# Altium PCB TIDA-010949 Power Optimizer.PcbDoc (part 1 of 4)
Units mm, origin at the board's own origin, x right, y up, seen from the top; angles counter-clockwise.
Board outline 129.4 x 84 mm, 4 copper layers (Power1, Ground1, Ground2, Power2), stack 1.926 mm thick; 265 components, 128 nets, 802 pads, 1069 vias.
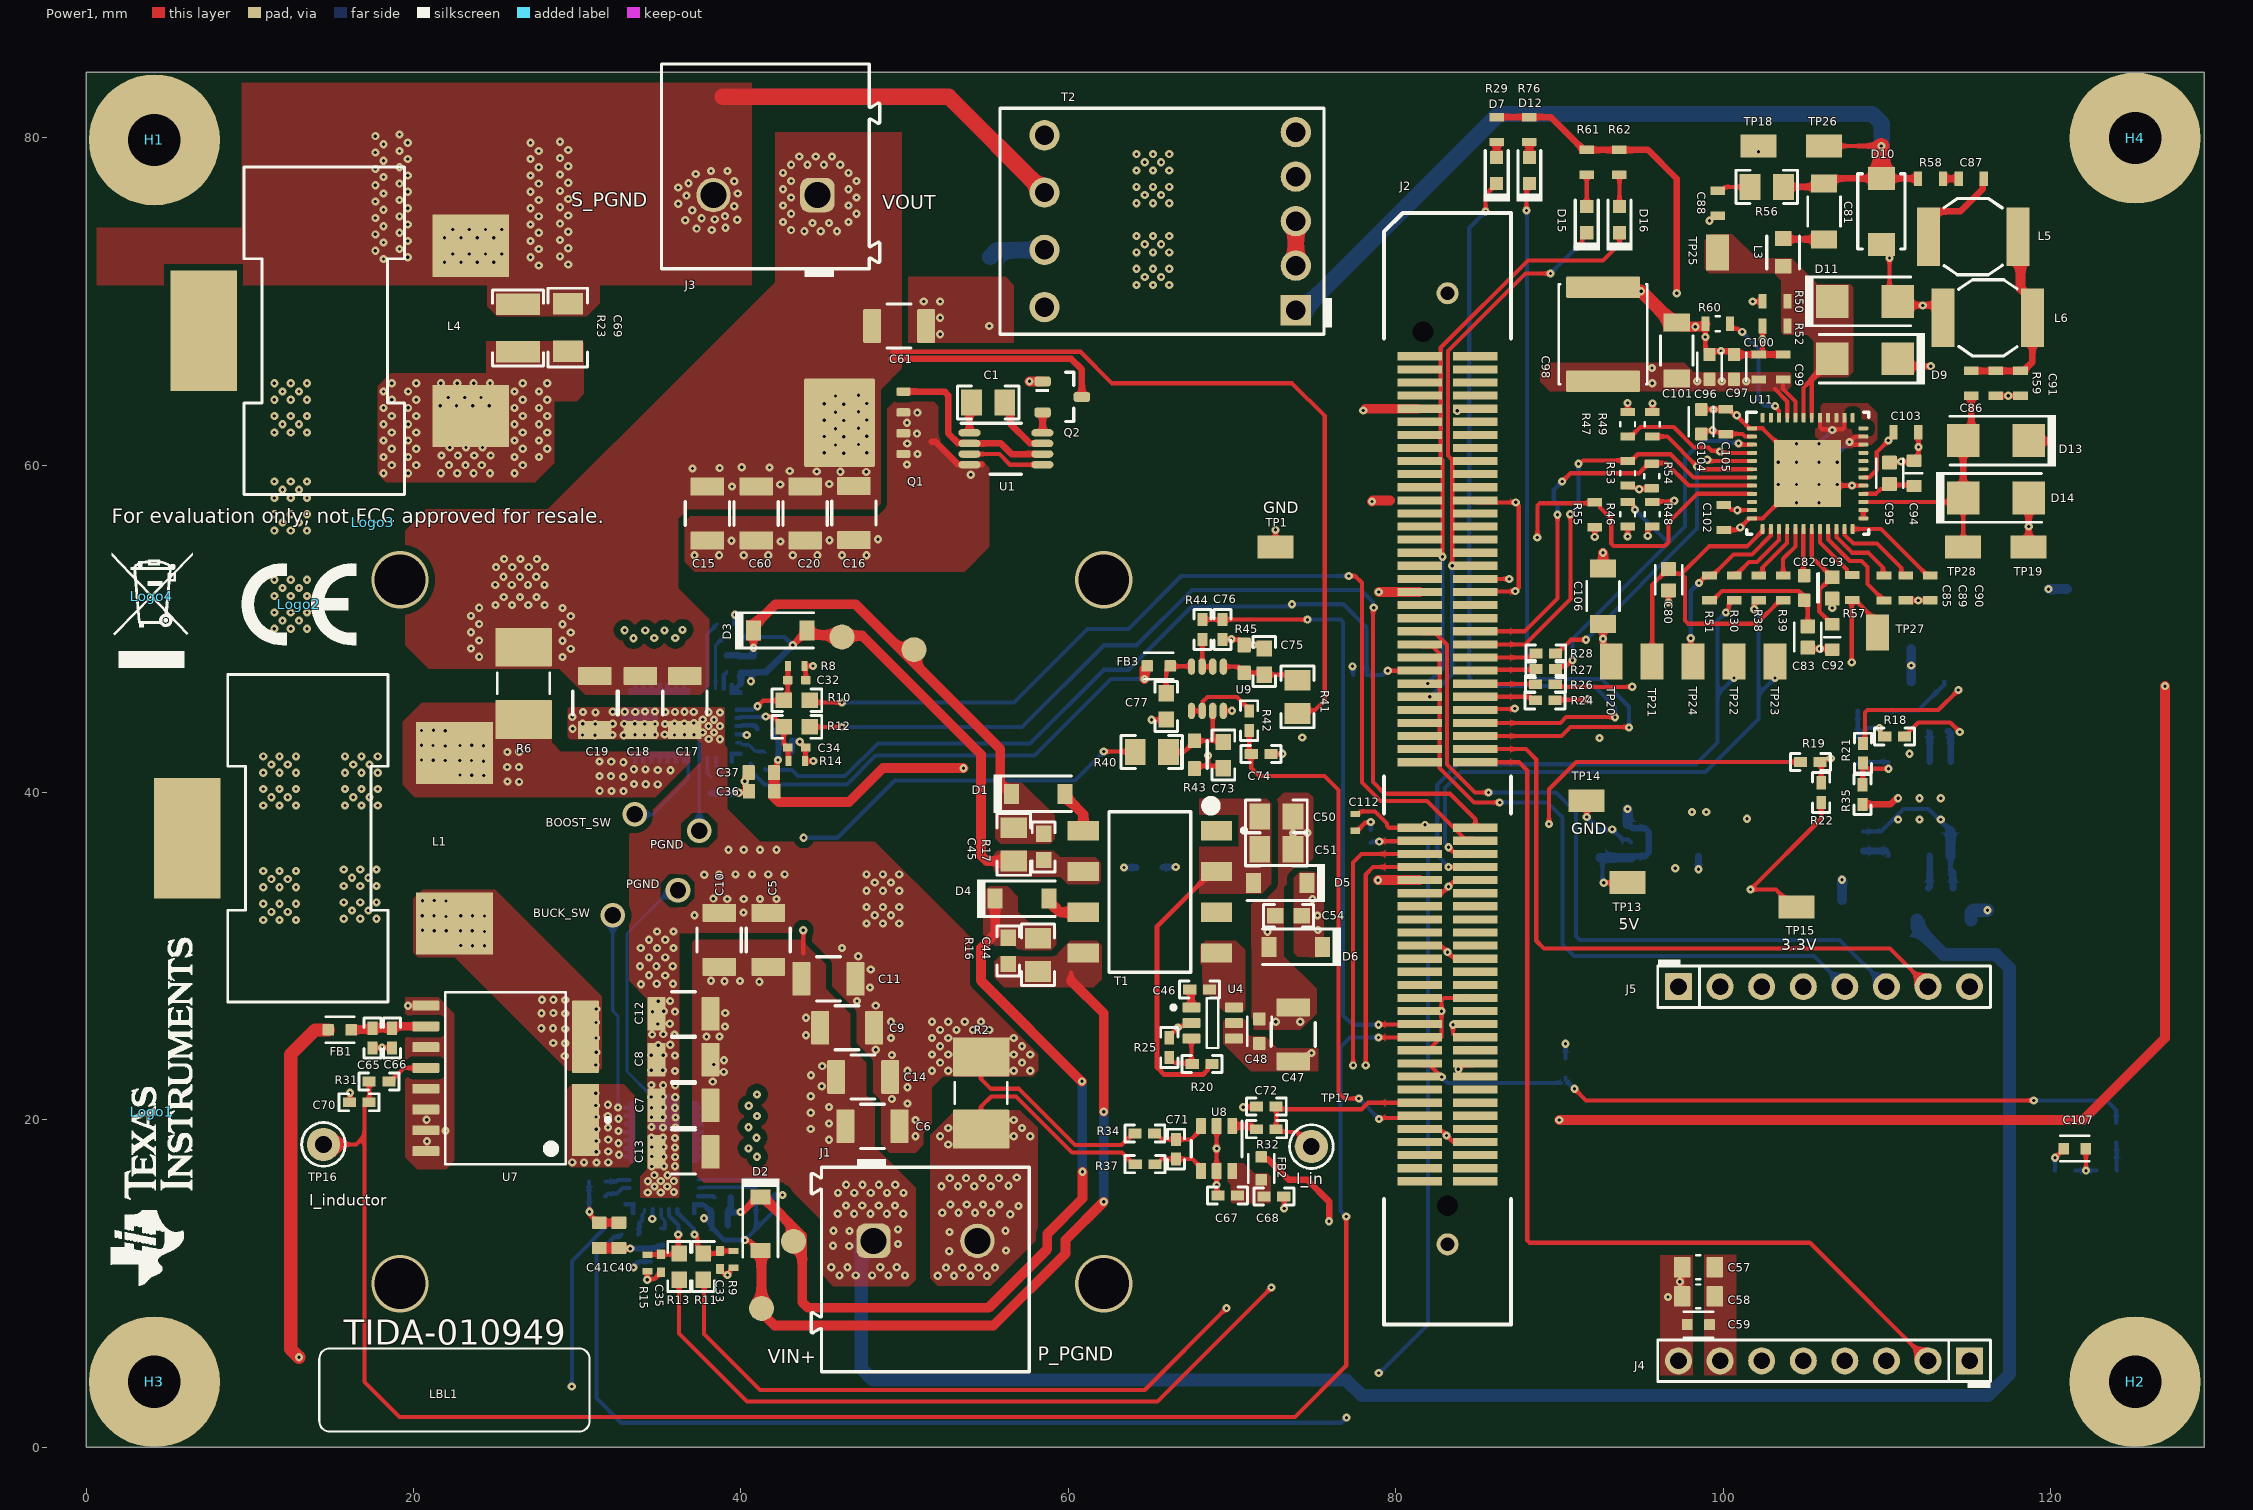
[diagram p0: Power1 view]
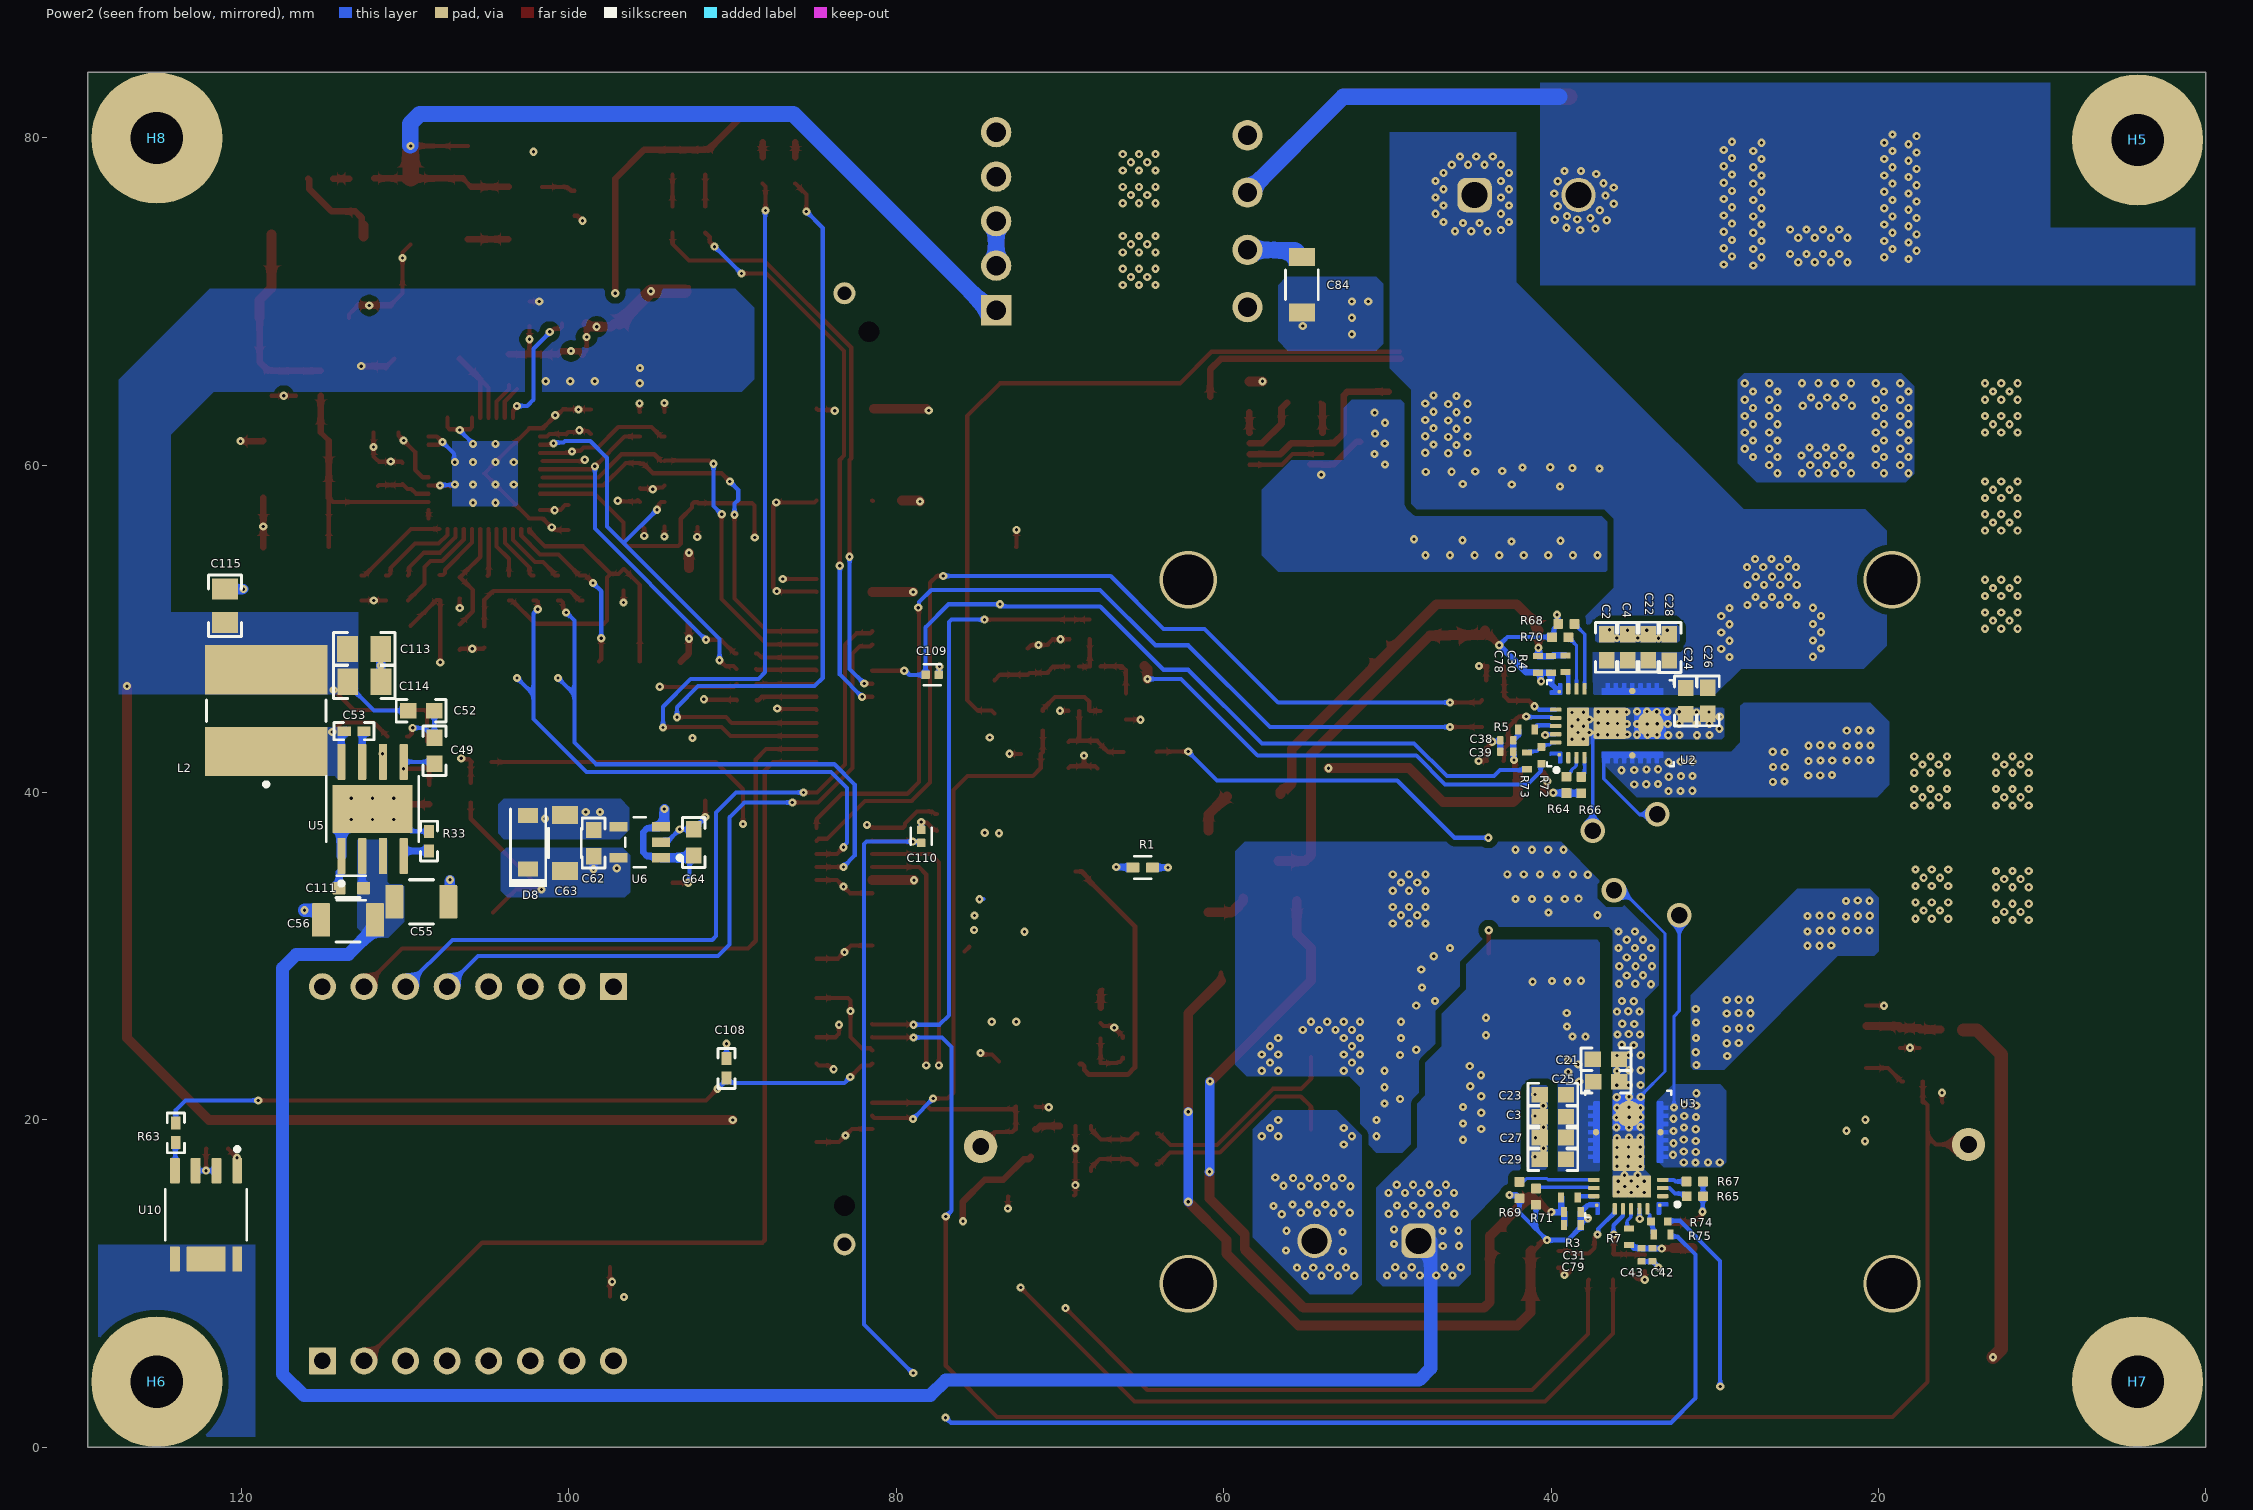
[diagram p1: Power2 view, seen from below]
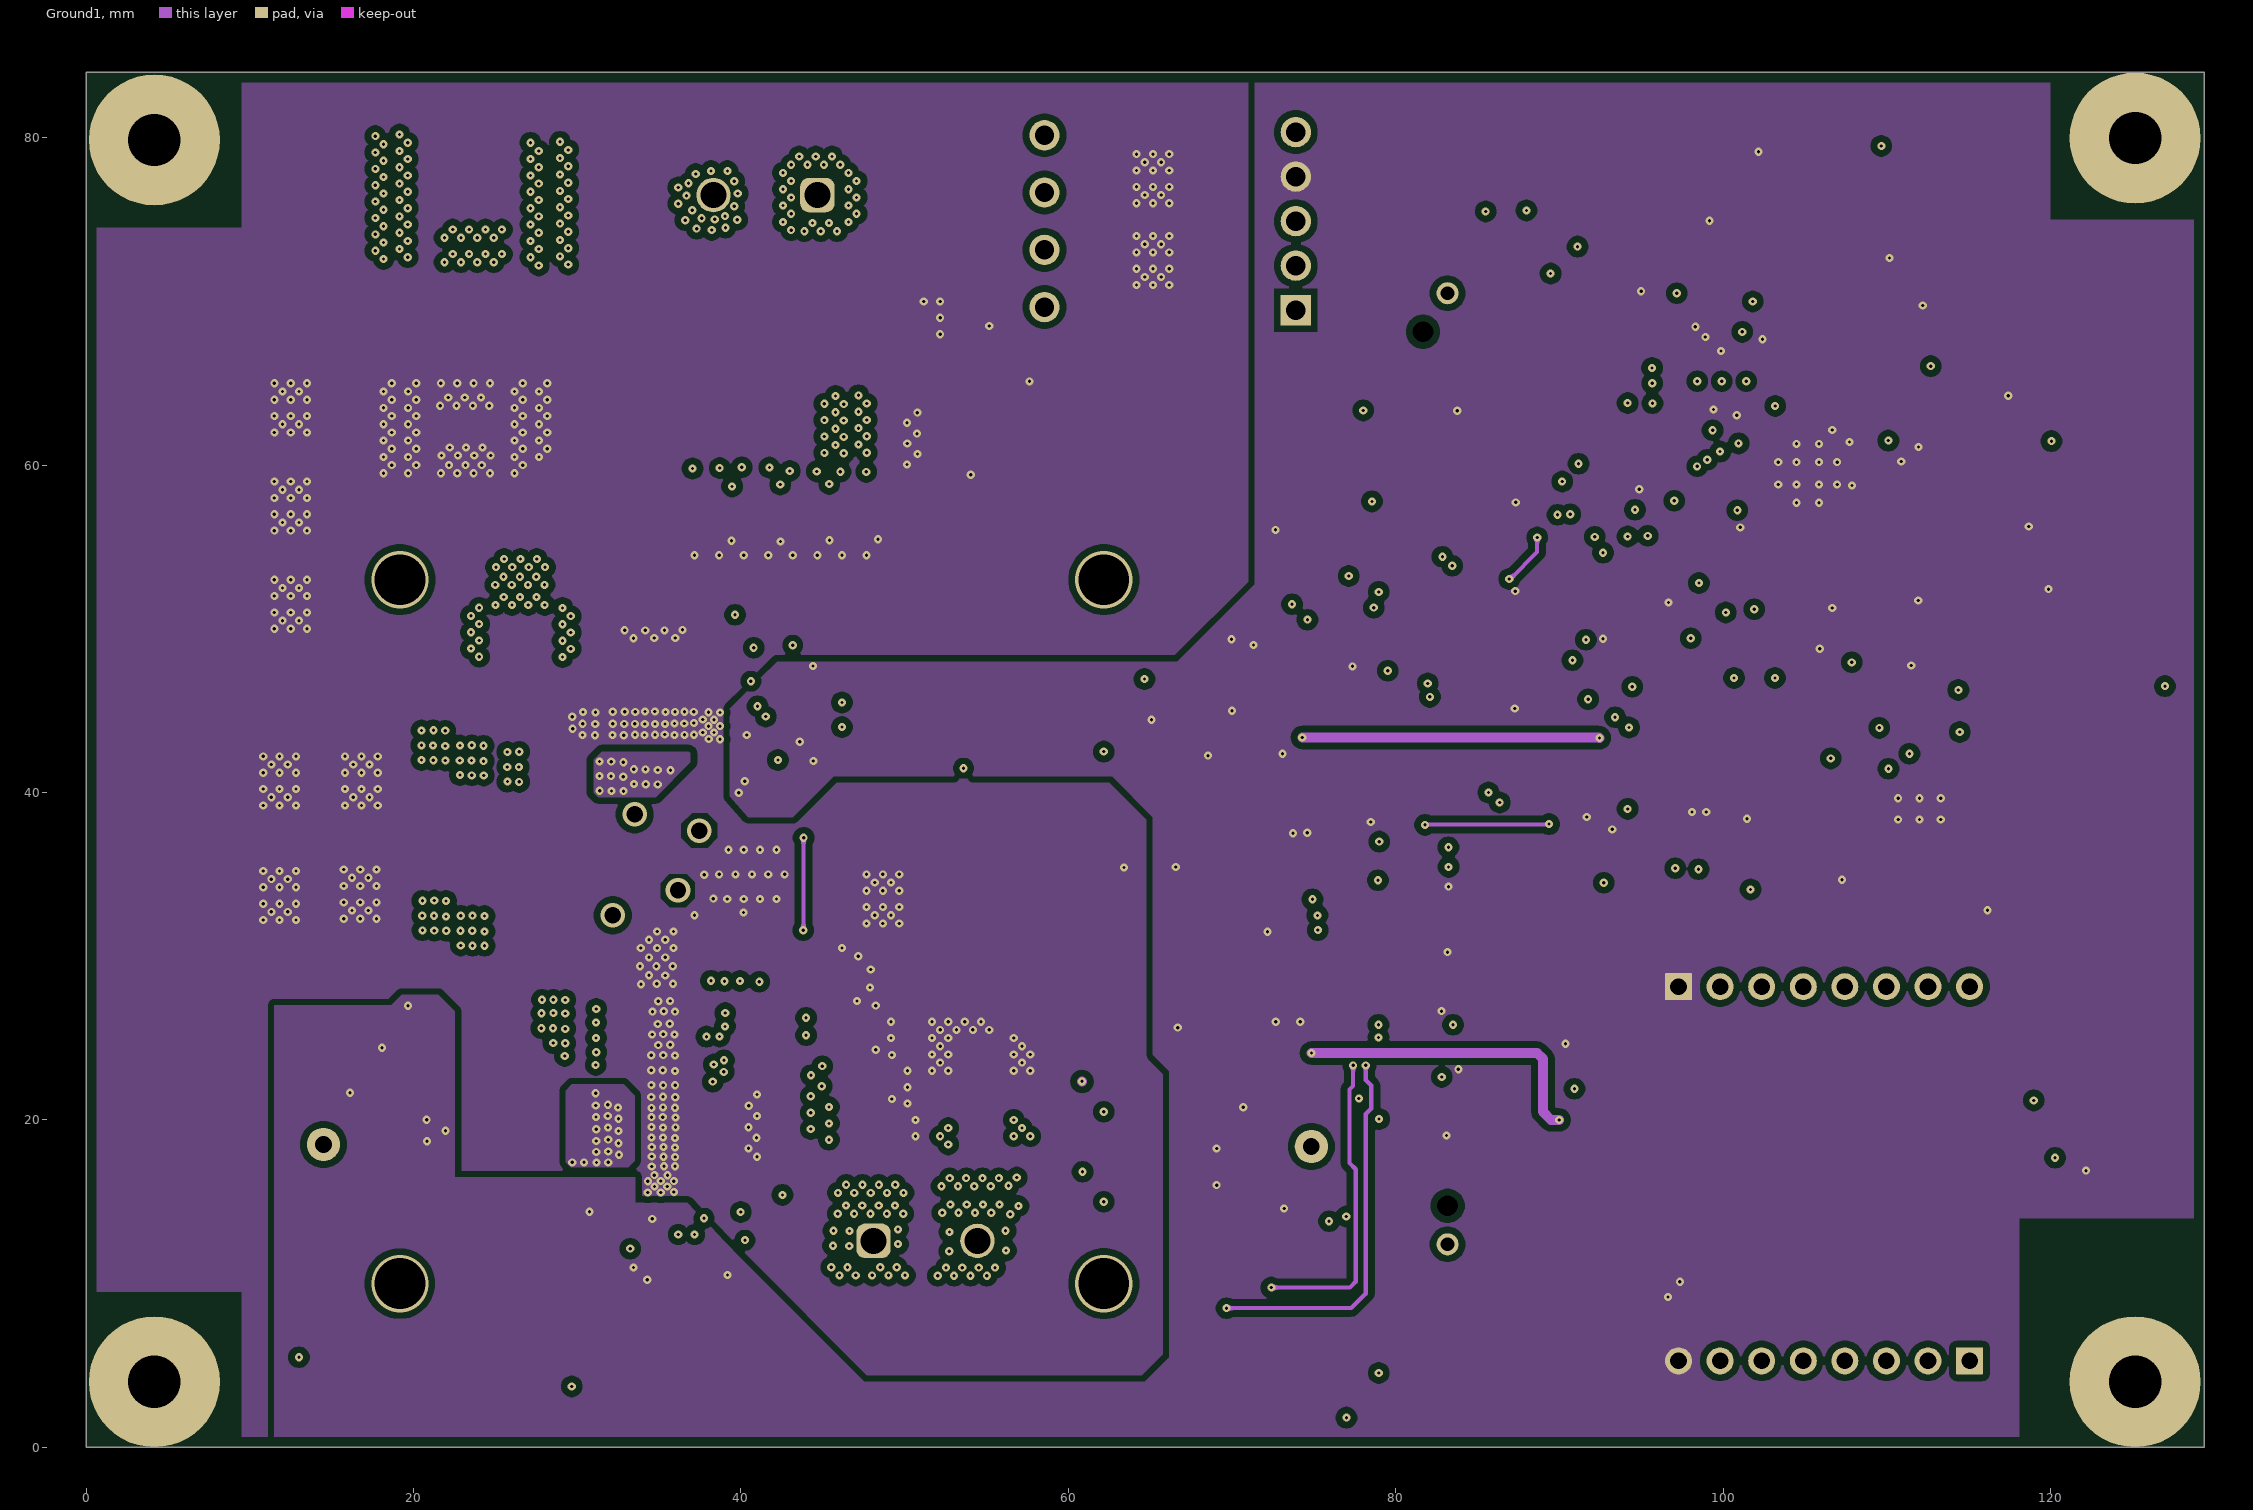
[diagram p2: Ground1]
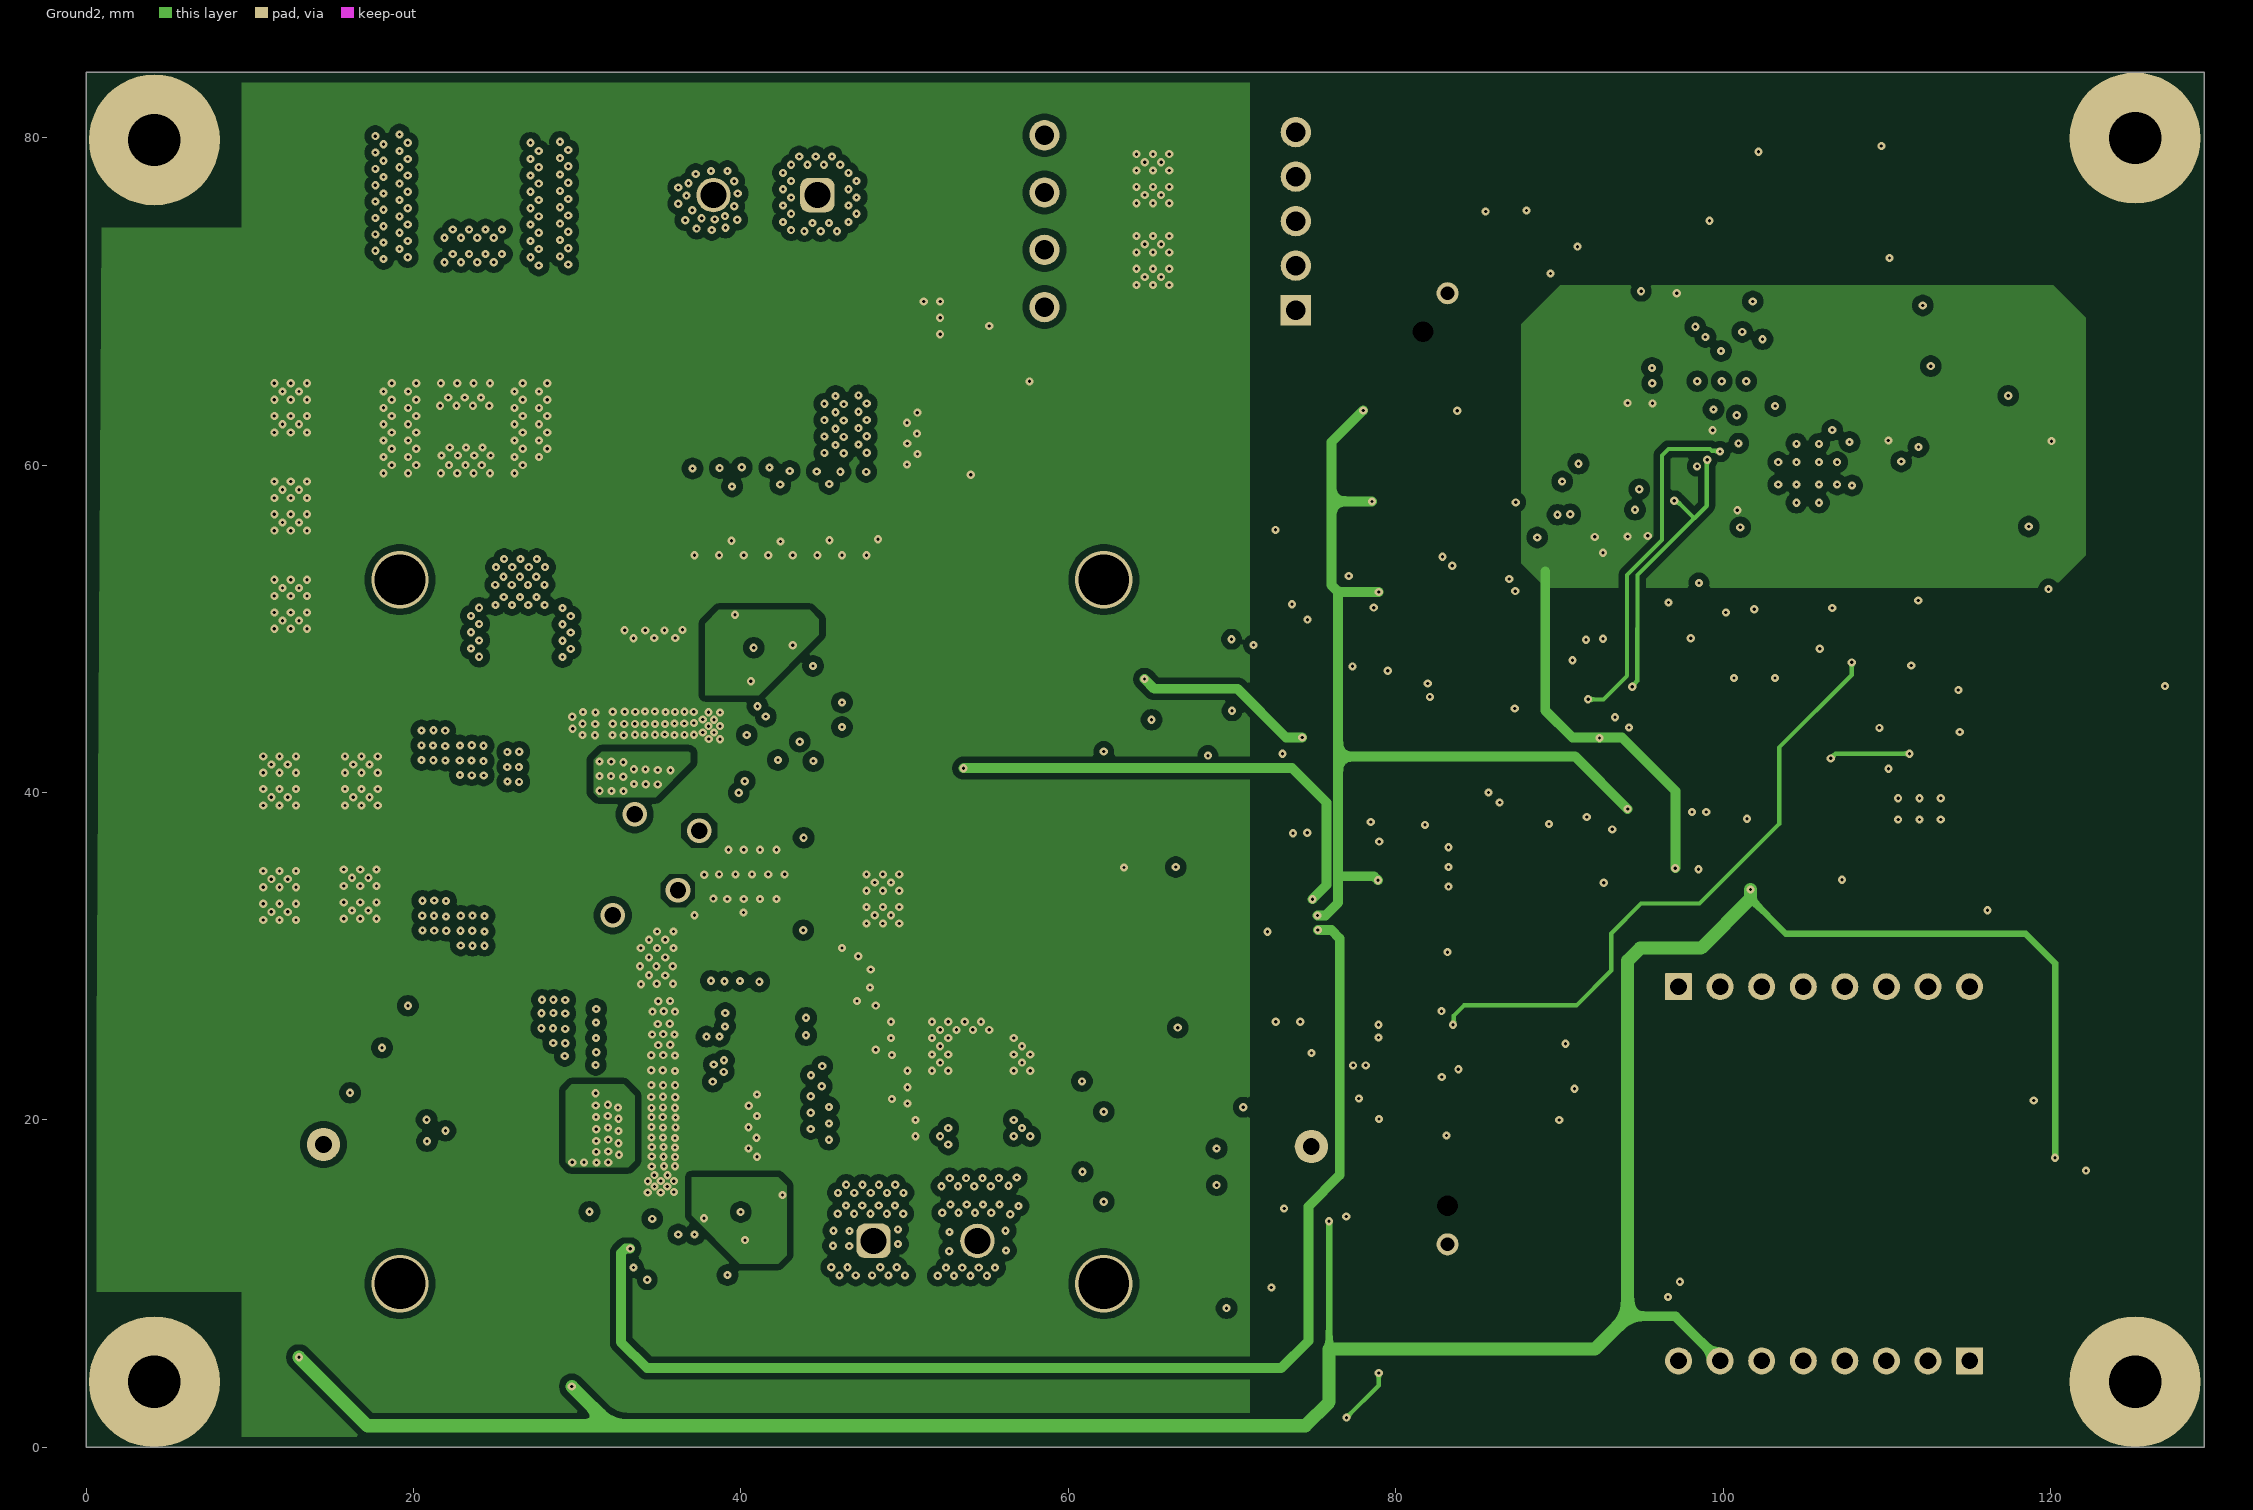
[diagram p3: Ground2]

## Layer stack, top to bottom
Top Solder: solder mask 0.0102, Solder Resist, Dk 3.5
Power1: signal copper 0.07
Dielectric 1: prepreg 0.0711, PP-006, Dk 4.1
Ground1: signal copper 0.07
Dielectric1: core 1.5037, FR-4 High Tg, Dk 4.8
Ground2: signal copper 0.07
Dielectric 2: prepreg 0.0711, PP-006, Dk 4.1
Power2: signal copper 0.07
Bottom Solder: solder mask 0.0102, Solder Resist, Dk 3.5

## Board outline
0,0 0,84 129.401,84 129.401,0

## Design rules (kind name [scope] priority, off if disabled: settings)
AcuteAngle [All] p1: minimum=4.40000000000000E+0001 checktracksonly=FALSE
AssemblyTestPointUsage [All] p1: valid=2
BoardOutlineClearance BoardOutlineClearance_MountingHoles [OnCopper and InComponentClass('Mounting Holes')] p1: gap=1 ignorepadtopadclearanceinfootprint=FALSE
BoardOutlineClearance BoardOutlineClearance_Poly [OnCopper and IsPoly] p2: gap=0.635 ignorepadtopadclearanceinfootprint=FALSE
BoardOutlineClearance [OnCopper and Not InComponentClass('Logo') and not InComponentClass('FiducialMark') and not InRegion(1000,500,4000,800) and not InPoly] p3: gap=0.416 ignorepadtopadclearanceinfootprint=FALSE
Clearance Clearance_Keepouts [((IsTrack Or IsArc) And Not InPoly) And IsFree and IsKeepOut vs ((IsTrack Or IsArc) And Not InPoly) And IsFree and IsKeepOut] p1: gap=0 ignorepadtopadclearanceinfootprint=FALSE
Clearance Clearance_Poly [InPolygon] p2: gap=0.4 ignorepadtopadclearanceinfootprint=TRUE
Clearance Clearance_FiducialMark [IsKeepOut and InComponentClass('FiducialMark') vs IsPad and InComponentClass('FiducialMark')] p3: gap=0 ignorepadtopadclearanceinfootprint=FALSE
Clearance [All] p4: gap=0.2 ignorepadtopadclearanceinfootprint=TRUE except(0.18: Arc-Arc Arc-Track Track-Track)
ComponentClearance ComponentClearance_MountingHoles_FiducialMarks [InComponentClass('Mounting Holes') vs InComponentClass('FiducialMark')] p1: gap=1.27 collisioncheckmode=3 verticalgap=0.254 showdistances=FALSE
ComponentClearance ComponentClearance_Shunt [InComponentClass('Header') vs InComponentClass('Shunt')] p2: gap=0 collisioncheckmode=3 verticalgap=0 showdistances=FALSE
ComponentClearance ComponentClearance_Logo [InComponentClass('Logo')] p3: gap=0.762 collisioncheckmode=3 verticalgap=0.254 showdistances=FALSE
ComponentClearance ComponentClearance_ScrewToNut [(HasFootprint('NY PMS 440 0025 PH')) vs (HasFootprint('Keystone_1902C'))] p4: gap=0.127 collisioncheckmode=3 verticalgap=0.254 showdistances=FALSE
ComponentClearance ComponentClearance_MountingHoles [InComponentClass('Mounting Holes')] p5: gap=1.5 collisioncheckmode=3 verticalgap=2540 showdistances=FALSE
ComponentClearance ComponentClearance_SmallPassives [HasFootprint('0201*') or HasFootprint('0402*') or HasFootprint('0508') or HasFootprint('0603*') or HasFootprint('0612') or HasFootprint('0805*') or HasFootprint('0815*') or HasFootprint('0830*') or HasFootprint('1206*') or HasFootprint('1210*') or HasFootprint('1808*') or HasFootprint('1812*') or HasFootprint('1825*') or HasFootprint('2010*') or HasFootprint('2220*') or HasFootprint('2225*') or HasFootprint('2512*') or HasFootprint('2728*') or HasFootprint('3518*') vs HasFootprint('0201*') or HasFootprint('0402*') or HasFootprint('0508') or HasFootprint('0603*') or HasFootprint('0612') or HasFootprint('0805*') or HasFootprint('0815*') or HasFootprint('0830*') or HasFootprint('1206*') or HasFootprint('1210*') or HasFootprint('1808*') or HasFootprint('1812*') or HasFootprint('1825*') or HasFootprint('2010*') or HasFootprint('2220*') or HasFootprint('2225*') or HasFootprint('2512*') or HasFootprint('2728*') or HasFootprint('3518*')] p6: gap=0.1 collisioncheckmode=3 verticalgap=0.1 showdistances=FALSE
ComponentClearance ComponentClearance_THtoSMT [IsThruComponent vs IsSMTComponent] p7: gap=0.2 collisioncheckmode=3 verticalgap=0.762 showdistances=FALSE
ComponentClearance ComponentClearance_THtoTH [IsThruComponent vs IsThruComponent] p8: gap=0.508 collisioncheckmode=3 verticalgap=0.762 showdistances=FALSE
ComponentClearance [All] p9: gap=0.1 collisioncheckmode=3 verticalgap=0.254 showdistances=FALSE
DiffPairsRouting [All] p1: maxlimit=2.54 minlimit=0.254 mostfreqgap=0.254 toplayer_minwidth=0.381 toplayer_maxwidth=0.381 toplayer_prefwidth=0.381 midlayer1_minwidth=0.381 midlayer1_maxwidth=0.381 midlayer1_prefwidth=0.381 midlayer2_minwidth=0.381 midlayer2_maxwidth=0.381 midlayer2_prefwidth=0.381 bottomlayer_minwidth=0.381 bottomlayer_maxwidth=0.381 bottomlayer_prefwidth=0.381 maxuncoupledlength=25.4
FabricationTestPointUsage TestPointUsage [All] p1: valid=2 allowmultiple=FALSE
FabricationTestpoint Testpoint [All] p1: side=3 testpointundercomponent=TRUE minsize=1.016 maxsize=2.54 preferedsize=1.524 minholesize=0 maxholesize=1.016 preferedholesize=0.813 testpointgrid=0.025 allowsidetop=TRUE allowsidebottom=TRUE usegrid=TRUE gridtolerance=0
FanoutControl Fanout_LCC [IsLCC] p1: bgadir=Out bgaviamode=Centered fanoutstyle=Auto fanoutdirection=Alternating viagrid=0.025 // Fanout_LCC (Default Rule)
FanoutControl Fanout_BGA [IsBGA] p2: bgadir=Out bgaviamode=Centered fanoutstyle=Auto fanoutdirection=Alternating viagrid=0.025 // Fanout_BGA (Default Rule)
FanoutControl Fanout_Default [All] p4: bgadir=Out bgaviamode=Centered fanoutstyle=Auto fanoutdirection=Alternating viagrid=0.025 // Fanout_Default (Default Rule)
FanoutControl Fanout_Small [(CompPinCount < 5)] p5: bgadir=Out bgaviamode=Centered fanoutstyle=Auto fanoutdirection=OutThenIn viagrid=0.025 // Fanout_Small (Default Rule)
HoleSize [All] p1: absolutevalues=TRUE maxlimit=6.375 minlimit=0.2 maxpercent=80.000 minpercent=20.000
MinimumAnnularRing MinimumAnnularRing_ThermalPadVias [IsVia and InAnyComponent] p1: minimumring=0.1
MinimumAnnularRing [All] p2: minimumring=0.1
MinimumSolderMaskSliver MinimumSolderMaskSliver_Logo [InComponentClass('Logo') vs InComponentClass('Logo')] p1: minsoldermaskwidth=0.018
MinimumSolderMaskSliver [All] p2: minsoldermaskwidth=0.08
PlaneConnect [All] p1: planeconnectstyle=Relief reliefexpansion=0.254 reliefentries=4 reliefconductorwidth=0.254 reliefairgap=0.254
PolygonConnect [All] p1: connectstyle=Direct reliefconductorwidth=0.254 reliefentries=4 polygonreliefangle="90 Angle" airgapwidth=0.254
RoutingVias ThermalPadVias [IsVia and InAnyComponent] p1: holewidth=0.2 width=0.5 viastyle="Through Hole" minholewidth=0.2 minwidth=0.5 maxholewidth=0.33 maxwidth=0.8
RoutingVias [All] p2: holewidth=0.406 width=0.864 viastyle="Through Hole" minholewidth=0.2 minwidth=0.5 maxholewidth=1.016 maxwidth=1.651
SilkToBoardRegionClearance [Not ((IsComment or IsDesignator) And (Hide <> 'False')) and not InRegion(1000,500,4000,800)] p1:
SilkToSilkClearance SilkToSilkClearance_Pb-FreeLogo [(HasFootprint('Pb-Free_Overlay_Medium') OR HasFootprint('Pb-Free_Overlay_Small')) vs (HasFootprint('Pb-Free_Overlay_Medium') OR HasFootprint('Pb-Free_Overlay_Small'))] p1: silktosilkclearance=0
SilkToSilkClearance [All] p2: silktosilkclearance=0
SilkToSolderMaskClearance SilkToComponentPadClearance [(IsPad or IsFill or IsRegion) and InAnycomponent] p1: minsilkscreentomaskgap=0 clearancetoexposedcopper=TRUE
SilkToSolderMaskClearance "Silk to Solder Mask Opening" [All] p2: minsilkscreentomaskgap=0 clearancetoexposedcopper=FALSE
SolderMaskExpansion [All] p1: expansion=0.05 istentingtop=FALSE
UnRoutedNet [All] p1: checkbadconnections=TRUE
Width [All] p1: maxlimit=2.54 minlimit=2539.975 preferedwidth=0.254 toplayer_minwidth=0 midlayer1_minwidth=0 midlayer2_minwidth=0 bottomlayer_minwidth=0 minimp=50.000000 maximp=50.000000 favimp=50.000000 checkconnectedcopper=TRUE
14 further rules are at their usual default settings.

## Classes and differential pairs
component class "U_TIDA-010949 Power Optimizer_Wireless": C57 C58 C59 J4 J5
component class Header: J4 J5
component class "U_TIDA-010949 Power Optimizer_PLC": C69 C80 C81 C82 C83 C84 C85 C86 C87 C88 C89 C90 C91 C92 C93 C94 C95 C96 C97 C98 C99 C100 C101 C102 C103 C104 C105 C106 D9 D10 D11 D13 D14 D15 D16 L3 L4 L5 L6 R23 R30 R38 R39 R46 R47 R48 R49 R50 R51 R52 R53 R54 R55 R56 R57 R58 R59 R60 R61 R62 T2 TP18 TP19 TP20 TP21 TP22 TP23 TP24 TP25 TP26 TP27 TP28 U11 U12
component class "TIDA-010949 Power Optimizer_Top View": J1 J3
component class "U_TIDA-010949 Power Optimizer_Sampling": C65 C66 C67 C68 C70 C71 C72 C73 C74 C75 C76 C77 C107 C108 FB1 FB2 FB3 R31 R32 R34 R37 R40 R41 R42 R43 R44 R45 R63 TP16 TP17 U7 U8 U9 U10
component class "U_TIDA-010949 Power Optimizer_MCU": D7 D12 J2 R24 R26 R27 R28 R29 R76
component class "U_TIDA-010949 Power Optimizer_Aux": C44 C45 C46 C47 C48 C49 C50 C51 C52 C53 C54 C55 C56 C62 C63 C64 C111 C112 C113 C114 C115 D1 D2 D3 D4 D5 D6 D8 L2 R16 R17 R18 R19 R20 R21 R22 R25 R33 R35 T1 TP13 TP14 TP15 U4 U5 U6
component class "Mounting Holes": H1 H2 H3 H4
component class Logo: Logo1
component class "U_TIDA-010949 Power Optimizer_Hardware": H1 H2 H3 H4 H5 H6 H7 H8 LBL1 Logo1 Logo2 Logo3 Logo4
component class Label: LBL1

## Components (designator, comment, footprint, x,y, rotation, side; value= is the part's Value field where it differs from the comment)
C1 "0805YD225KAT2A" 0805_HV 55.109,63.825 r180 top value=2.2uF
C2 "HMK107C7224KAHTE" 0603 36.602,48.874 r270 bottom value=0.22uF
C3 "HMK107C7224KAHTE" 0603 39.895,20.2 r180 bottom value=0.22uF
C4 "HMK107C7224KAHTE" 0603 35.32,48.874 r270 bottom value=0.22uF
C5 "GRM32EC72A106KE05L" FP-GRM32EC72A106KE05L_1210-MFG 41.674,31 r270 top
C6 "GRM32EC72A106KE05L" FP-GRM32EC72A106KE05L_1210-MFG 48.03,19.608 r180 top
C7 "GRM32EC72A106KE05L" FP-GRM32EC72A106KE05L_1210-MFG 36.493,20.889 r0 top
C8 "GRM32EC72A106KE05L" FP-GRM32EC72A106KE05L_1210-MFG 36.493,23.686 r0 top
C9 "GRM32EC72A106KE05L" FP-GRM32EC72A106KE05L_1210-MFG 46.494,25.632 r180 top
C10 "GRM32EC72A106KE05L" FP-GRM32EC72A106KE05L_1210-MFG 38.674,31 r270 top
C11 "GRM32EC72A106KE05L" FP-GRM32EC72A106KE05L_1210-MFG 45.345,28.616 r180 top
C12 "GRM32EC72A106KE05L" FP-GRM32EC72A106KE05L_1210-MFG 36.493,26.475 r0 top
C13 "GRM32EC72A106KE05L" FP-GRM32EC72A106KE05L_1210-MFG 36.493,18.042 r0 top
C14 "GRM32EC72A106KE05L" FP-GRM32EC72A106KE05L_1210-MFG 47.475,22.622 r180 top
C15 "GRM32EC72A106KE05L" FP-GRM32EC72A106KE05L_1210-MFG 37.951,57.042 r90 top
C16 "GRM32EC72A106KE05L" FP-GRM32EC72A106KE05L_1210-MFG 46.906,57.07 r90 top
C17 "GRM32EC72A106KE05L" FP-GRM32EC72A106KE05L_1210-MFG 36.578,45.466 r90 top
C18 "GRM32EC72A106KE05L" FP-GRM32EC72A106KE05L_1210-MFG 33.863,45.466 r90 top
C19 "GRM32EC72A106KE05L" FP-GRM32EC72A106KE05L_1210-MFG 31.078,45.466 r90 top
C20 "GRM32EC72A106KE05L" FP-GRM32EC72A106KE05L_1210-MFG 43.921,57.059 r90 top
C21 "HMK107C7224KAHTE" 0603 36.651,23.699 r0 bottom value=0.22uF
C22 "HMK107C7224KAHTE" 0603 34.075,48.881 r270 bottom value=0.22uF
C23 "HMK107C7224KAHTE" 0603 39.895,21.547 r180 bottom value=0.22uF
C24 "HMK107C7224KAHTE" 0603 31.767,45.588 r90 bottom value=0.22uF
C25 "HMK107C7224KAHTE" 0603 36.638,22.339 r0 bottom value=0.22uF
C26 "HMK107C7224KAHTE" 0603 30.42,45.603 r90 bottom value=0.22uF
C27 "HMK107C7224KAHTE" 0603 39.895,18.925 r180 bottom value=0.22uF
C28 "HMK107C7224KAHTE" 0603 32.771,48.866 r270 bottom value=0.22uF
C29 "HMK107C7224KAHTE" 0603 39.895,17.59 r180 bottom value=0.22uF
C30 "GRM155R71E104KE14D" 0402S 40.001,47.827 r270 bottom value=0.1uF
C31 "GRM155R71E104KE14D" 0402S 38.7,14.364 r180 bottom value=0.1uF
C32 "04025U100FAT2A" FP-04025U100FAT2A_0402-MFG 43.415,46.86 r180 top value=10pF
C33 "04025U100FAT2A" FP-04025U100FAT2A_0402-MFG 38.727,11.448 r90 top value=10pF
C34 "04025U100FAT2A" FP-04025U100FAT2A_0402-MFG 43.415,42.747 r180 top value=10pF
C35 "04025U100FAT2A" FP-04025U100FAT2A_0402-MFG 35.12,11.239 r90 top value=10pF
C36 "GRM188C71C225KE11D" FP-GRM188C71C225KE11D_0603-MFG 41.269,40.078 r0 top value=2.2uF
C37 "GRM188C71C225KE11D" FP-GRM188C71C225KE11D_0603-MFG 41.252,41.218 r0 top value=2.2uF
C38 "GRT1555C1E101JA02D" FP-GRT1555C1E101JA02D_0402-MFG 42.707,43.195 r180 bottom value=100pF
C39 "GRT155R61E105KE01D" FP-GRT155R61E105KE01D_0402-MFG 42.707,42.495 r180 bottom value=1µF
C40 "GRM188C71C225KE11D" FP-GRM188C71C225KE11D_0603-MFG 32.551,12.947 r270 top value=2.2uF
C41 "GRM188C71C225KE11D" FP-GRM188C71C225KE11D_0603-MFG 31.344,12.947 r270 top value=2.2uF
C42 "GRT1555C1E101JA02D" FP-GRT1555C1E101JA02D_0402-MFG 33.813,11.751 r90 bottom value=100pF
C43 "GRT155R61E105KE01D" FP-GRT155R61E105KE01D_0402-MFG 34.476,11.751 r90 bottom value=1µF
C44 "0805YD106KAT2A" 0805_HV 58.155,30.085 r90 top value=10uF
C45 "0805YD106KAT2A" 0805_HV 56.675,36.829 r90 top value=10uF
C46 "0402YC104KAT2A" 0402 68.024,27.968 r180 top value=0.1uF
C47 "GRM32EC72A106KE05L" FP-GRM32EC72A106KE05L_1210-MFG 73.739,25.224 r270 top
C48 "06031C104K4T2A" FP-06031C104K4T2A_0603-MFG 71.674,25.418 r270 top value=100nF
C49 "GRM1885C2A201JA01D" 0603 108.217,42.553 r90 bottom value=200pF
C50 "0805YD106KAT2A" 0805_HV 72.719,38.53 r0 top value=10uF
C51 "0805YD106KAT2A" 0805_HV 72.719,36.53 r0 top value=10uF
C52 "GRM188R72A222KA01D" 0603 109.03,45.002 r180 bottom value=2200pF
C53 "GRM155R71H222KA01D" 0402 113.129,43.747 r180 bottom value=2200pF
C54 "06033C104JAT2A" 0603 73.457,32.473 r180 top value=0.1uF
C55 "GRM32EC72A106KE05L" FP-GRM32EC72A106KE05L_1210-MFG 109.025,33.322 r0 bottom
C56 "GRM32EC72A106KE05L" FP-GRM32EC72A106KE05L_1210-MFG 113.497,32.22 r180 bottom
C57 "0805YC106KAT2A" FP-0805YC106KAT2A_0805-MFG 98.5,11 r0 top value=10µF
C58 "0805YC106KAT2A" FP-0805YC106KAT2A_0805-MFG 98.5,9.221 r0 top value=10µF
C59 "GCJ188R71C104KA01D" FP-GCJ188R71C104KA01D_0603-MFG 98.5,7.5 r0 top value=100nF
C60 "GRM32EC72A106KE05L" FP-GRM32EC72A106KE05L_1210-MFG 40.935,57.055 r90 top
C61 "GRM32EC72A106KE05L" FP-GRM32EC72A106KE05L_1210-MFG 49.674,68.5 r180 top
C62 "C1608X7R1E105K080AB" 0603 98.499,36.913 r90 bottom value=1uF
C63 "GRM31CR71E106KA12L" 1206_180 100.249,36.913 r90 bottom value=10uF
C64 "C1608X7R1E105K080AB" 0603 92.382,36.95 r90 bottom value=1uF
C65 "GRM155R71E104KE14D" 0402 17.5,25 r270 top value=0.1uF
C66 "GRM155R61E105MA12D" 0402 18.686,25 r270 top value=1uF
C67 "GRM155R71E104KE14D" 0402 69.737,15.373 r180 top value=0.1uF
C68 "GRM155R61E105MA12D" 0402 72.564,15.326 r0 top value=1uF
C69 "C1206C394K1RAC7800" 1206 29.433,68.408 r90 top value=0.39uF
C70 "GRM1555C1E471JA01D" 0402 16.68,21.079 r180 top value=470pF
C71 "GRM155R71E103KA01D" 0402 66.584,18.213 r270 top value=0.01uF
C72 "GRM1555C1E471JA01D" 0402 72.099,20.821 r180 top value=470pF
C73 "CC0603JRNPO8BN102" 0603 69.479,42.29 r270 top value=1000pF
C74 "GRM1555C1H301JA01D" 0402 71.779,42.345 r0 top value=300pF
C75 "CC0603JRNPO8BN102" 0603 71.974,48 r90 top value=1000pF
C76 "GRM1555C1H301JA01D" 0402 69.427,49.961 r270 top value=300pF
C77 "06033C104JAT2A" 0603 65.982,45.262 r90 top value=0.1uF
C78 "GRM155R61E105KA12D" 0402S 40.794,47.827 r270 bottom value=1uF
C79 "GRM155R61E105KA12D" 0402S 38.7,13.569 r180 bottom value=1uF
C80 "C0603X102K5RAC7867" FP-C0603X102K5RAC7867_0603-MFG 96.674,53 r90 top value=1nF
C81 "GRT31CR61H106KE01L" 1206_180 106.174,75.5 r270 top value=10uF
C82 "06031C332J4Z2A" FP-06031C332J4Z2A_0603-MFG 104.962,52.496 r270 top
C83 "C0603X102K5RAC7867" FP-C0603X102K5RAC7867_0603-MFG 105.174,49.5 r90 top value=1nF
C84 "CGA5L2X7R2A105K160AA" 1206_180 55.229,71.02 r90 bottom value=1uF
C85 "GRM188R71H103KA01D" 0603S 109.837,52.495 r270 top value=0.01uF
C86 "885012206089" 0603S 115.174,65 r270 top value=0.01uF
C87 "GRM1885C1H182JA01D" 0603S 115.174,77.5 r0 top value=1800pF
C88 "06035A102KAT2A" 0603S 99.674,76 r270 top value=1000pF
C89 "GRM1885C1E561JA01D" 0603S 111.174,52.5 r270 top value=560pF
C90 "GRM1885C1H271JA01D" 0603S 112.674,52.5 r270 top value=270pF
C91 "06031C122JAT2A" 0603S 118.174,65 r270 top value=1200pF
C92 "GCM188D71H105KE36J" FP-GCM188D71H105KE36J_0603-MFG 106.674,49.5 r90 top value=1µF
C93 "C0603X102K5RAC7867" FP-C0603X102K5RAC7867_0603-MFG 106.674,52.5 r90 top value=1nF
C94 "GCM188D71H105KE36J" FP-GCM188D71H105KE36J_0603-MFG 111.674,59.5 r270 top value=1µF
C95 "C0603X102K5RAC7867" FP-C0603X102K5RAC7867_0603-MFG 110.174,59.5 r270 top value=1nF
C96 "06031C104K4T2A" FP-06031C104K4T2A_0603-MFG 99.174,66 r270 top value=100nF
C97 "06031C104K4T2A" FP-06031C104K4T2A_0603-MFG 100.674,66 r270 top value=100nF
C98 "CGA9N3X7R1E476M230KB" FP-CGA9N3X7R1E476M230KB_2220-MFG 92.674,68 r270 top value=47µF
C99 "885012206089" 0603S 103.674,66 r90 top value=0.01uF
C100 "885012206089" 0603S 102.174,66 r90 top value=0.01uF
C101 "GRT31CR61H106KE01L" 1206_180 97.174,67 r90 top value=10uF
C102 "885012206089" 0603S 100.045,56.8 r270 top value=0.01uF
C103 "885012206089" 0603S 111.174,62 r0 top value=0.01uF
C104 "06031C104K4T2A" FP-06031C104K4T2A_0603-MFG 98.67,62.65 r270 top value=100nF
C105 "885012206089" 0603S 100.17,62.65 r90 top value=0.01uF
C106 "GRT31CR61H106KE01L" 1206_180 92.674,52 r270 top value=10uF
C107 "GCJ188R71C104KA01D" FP-GCJ188R71C104KA01D_0603-MFG 121.488,18.238 r180 top value=100nF
C108 "GRM155R61A103KA01D" 0402 90.374,23.15 r90 bottom value=0.01uF
C109 "C0402C101J4GAC7867" FP-C0402C101J4GAC7867_0402-MFG 77.819,47.188 r0 bottom value=100pF
C110 "C0402C101J4GAC7867" FP-C0402C101J4GAC7867_0402-MFG 78.476,37.318 r270 bottom value=100pF
C111 "06031C104K4T2A" FP-06031C104K4T2A_0603-MFG 113.302,34.157 r180 bottom value=100nF
C112 "GRM155R71C104JA88D" 0402S 77.534,38.173 r270 top value=0.1uF
C113 "0805YD106KAT2A" 0805_HV 112.516,48.773 r180 bottom value=10uF
C114 "0805YD106KAT2A" 0805_HV 112.5,46.773 r180 bottom value=10uF
C115 "0805YD106KAT2A" 0805_HV 121.017,51.411 r90 bottom value=10uF
D1 "SD103AW-7-F" SOD-123 58.174,39.918 r0 top value=40V
D2 "MMSZ4689-E3-08" SOD-123 41.194,13.667 r270 top value=5.1V
D3 "MMSZ4689-E3-08" SOD-123 42.399,49.904 r0 top value=5.1V
D4 "SD103AW-7-F" SOD-123 57.174,33.518 r0 top value=40V
D5 "SD103AW-7-F" SOD-123 72.957,34.473 r180 top value=40V
D6 "MMSZ4689-E3-08" SOD-123 73.909,30.576 r180 top value=5.1V
D7 "150060BS75000" WL-SMCW_Blue 86.174,78 r90 top value=Blue
D8 "Zener" SOD-123 102.499,36.963 r90 bottom value=3.6V
D9 "B350A-13-F" SMA 108.674,66.5 r180 top value=50V
D10 "SMAJ22CA" SMA_Bi 109.674,75.5 r90 top value=22V
D11 "B350A-13-F" SMA 108.674,70 r0 top value=50V
D12 "150060RS75000" WL-SMCW_RED 88.174,78 r90 top value=Red
D13 "B350A-13-F" SMA 116.674,61.5 r180 top value=50V
D14 "B350A-13-F" SMA 116.674,58 r0 top value=50V
D15 "150060BS75000" WL-SMCW_Blue 91.674,75 r90 top value=Blue
D16 "150060RS75000" WL-SMCW_RED 93.674,75 r90 top value=Red
FB1 "MH1608-601Y" FP-MH1608-601Y_0603-MFG 15.5,25.5 r0 top
FB2 "MH1608-601Y" FP-MH1608-601Y_0603-MFG 71.789,17.037 r270 top
FB3 "MH1608-601Y" FP-MH1608-601Y_0603-MFG 65.532,47.731 r0 top
H1 "NY PMS 440 0025 PH" "NY PMS 440 0025 PH" 4.174,79.864 r0 top
H2 "NY PMS 440 0025 PH" "NY PMS 440 0025 PH" 125.174,4 r0 top
H3 "NY PMS 440 0025 PH" "NY PMS 440 0025 PH" 4.174,4 r0 top
H4 "NY PMS 440 0025 PH" "NY PMS 440 0025 PH" 125.174,79.986 r0 top
H5 "1902C" Keystone_1902C 4.174,79.864 r180 bottom
H6 "1902C" Keystone_1902C 125.174,4 r180 bottom
H7 "1902C" Keystone_1902C 4.174,4 r180 bottom
H8 "1902C" Keystone_1902C 125.174,79.986 r180 bottom
J1 "OSTT7020150" On-Shore_OSTT7020150 51.274,12.612 r0 top
J2 "HSEC8-160-01-L-DV-A-BL" controlCARD-120HSEC 83.196,39.607 r90 top
J3 "OSTT7020150" On-Shore_OSTT7020150 41.5,76.5 r180 top
J4 "TSW-108-07-G-S" TSW-108-07-G-S 106.174,5.278 r180 top
J5 "TSW-108-07-G-S" TSW-108-07-G-S 106.174,28.138 r0 top
L1 "SER2013-362MLB" SER2013 13.553,37.207 r180 top value=3.6uH
L2 "784787680" WE-PD2SA_7850 118.5,45 r90 bottom
L3 "LQH2MCN1R0M52" LQH2MC_52 103.674,73 r90 top value=1uH
L4 "SER2013-362MLB" SER2013 14.553,68.207 r180 top value=3.6uH
L5 "DO1607B-105MLB" DO1607B 115.291,73.961 r180 top value=1mH
L6 "DO1607B-155MLB" DO1607B 116.174,69 r0 top value=1.5mH
LBL1 "THT-14-423-10" Label_650x200 22.5,3.5 r0 top
Logo1 "Texas Instruments" TI_Stacked_Overlay_Small 4,20.5 r90 top
Logo2 "CE Mark" CE_Mark_5mm 13,51.5 r0 top
Logo3 "FCC disclaimer" FCC_disclaimer 17.5,56.5 r0 top
Logo4 "WEEE logo" WEEE_Minimum 4,52 r0 top
Q1 "CSD19532Q5B" DNK0008A 47.103,62.587 r180 top value=100V
Q2 "BSS169H6327XTSA1" SOT-23 59.634,64.168 r0 top value=100V
R1 "CR0402-10W-000T" FP-CR0402-10W-000T_0402-MFG 64.955,35.419 r180 bottom value=0uΩ
R2 "ULRG32512R001FLFSLT" FP-ULRG32512R001FLFSLT_2512-MFG 54.674,21.643 r90 top value=1m
R3 "CRCW04022R00FKED" 0402S 38.886,15.267 r180 bottom value=2.00
R4 "CRCW04022R00FKED" 0402S 39.131,47.868 r270 bottom value=2.00
R5 "CRCW04022R00FKED" 0402S 41.507,43.843 r180 bottom value=2.00
R6 "ULRG32512R001FLFSLT" FP-ULRG32512R001FLFSLT_2512-MFG 26.724,46.666 r270 top value=1m
R7 "CRCW04022R00FKED" 0402S 35.229,12.859 r90 bottom value=2.00
R8 "RC0402FR-0710K5L" 0402S 43.382,47.735 r0 top value=10.5k
R9 "RC0402FR-0710K5L" 0402S 39.536,11.482 r270 top value=10.5k
R10 "RC0603FR-0720RL" 0603 43.415,45.635 r180 top value=20.0
R11 "RC0603FR-0720RL" 0603 37.7,11.039 r90 top value=20.0
R12 "RC0603FR-0720RL" 0603 43.415,44.01 r180 top value=20.0
R13 "RC0603FR-0720RL" 0603 36.225,11.039 r90 top value=20.0
R14 "RC0402FR-0710K5L" 0402S 43.415,41.935 r0 top value=10.5k
R15 "RC0402FR-0710K5L" 0402S 34.283,11.258 r270 top value=10.5k
R16 "RC0603FR-071KL" 0603 56.338,30.325 r90 top value=1.00k
R17 "RC0603FR-071KL" 0603 58.491,36.679 r90 top value=1.00k
R18 "CRCW0402392KFKED" 0402 110.479,43.429 r180 top value=392k
R19 "CRCW040247R0JNED" 0402 105.337,41.86 r180 top value=47
R20 "CRCW040257K6FKED" 0402 68.174,23.418 r0 top value=57.6k
R21 "CRCW0402115KFKED" 0402 108.551,42.4 r90 top value=115k
R22 "CRCW040210K0JNED" 0402 106,40 r270 top value=10k
R23 "RC1210JR-075R6L" 1210 26.385,68.38 r270 top value=5.6
R24 "CRCW040247R0JNED" 0402 89.134,45.636 r180 top value=47
R25 "CRCW040210K0FKED" 0402 66.174,24.418 r270 top value=10.0k
R26 "CRCW040247R0JNED" 0402 89.149,46.619 r180 top value=47
R27 "CRCW040247R0JNED" 0402 89.17,47.552 r180 top value=47
R28 "CRCW040247R0JNED" 0402 89.174,48.5 r180 top value=47
R29 "RC0603JR-07680RL" 0603S 86.174,80.5 r90 top value=680
R30 "RC0603JR-0743KL" 0603S 100.674,52.5 r270 top value=43k
R31 "RK73H1ETTP47R0F" 0402 17.894,22.339 r180 top value=47.0
R32 "RK73H1ETTP47R0F" 0402 72.103,19.432 r0 top value=47.0
R33 "CRCW040260K4FKED" 0402 108.562,37.027 r270 bottom value=60.4k
R34 "RK73H1ETTP10R0F" 0402 64.679,19.178 r0 top value=10.0
R35 "CRCW040212K7FKED" 0402 108.526,39.874 r90 top value=12.7k
R37 "RK73H1ETTP10R0F" 0402 64.694,17.293 r0 top value=10.0
R38 "RC0603JR-0743KL" 0603S 102.174,52.5 r270 top value=43k
R39 "RC0603JR-07510RL" 0603S 103.674,52.5 r270 top value=510
R40 "RR1220P-3012-D-M" 0805_HV 65.113,42.48 r180 top value=30.1k
R41 "RR1220P-3012-D-M" 0805_HV 74.004,45.839 r270 top value=30.1k
R42 "CRCW040256R2FKED" 0402 71.054,44.387 r270 top value=56.2
R43 "RT0603BRD071KL" FP-RT0603BRD071KL_0603-MFG 67.711,42.314 r90 top value=1K
R44 "CRCW040256R2FKED" 0402 68.204,49.96 r90 top value=56.2
R45 "RT0603BRD071KL" FP-RT0603BRD071KL_0603-MFG 70.749,48.162 r270 top value=1K
R46 "CRCW060310K0JNEBC" FP-CRCW060310K0JNEBC_0603-MFG 94.174,57 r270 top value=10k
R47 "CRCW060310K0JNEBC" FP-CRCW060310K0JNEBC_0603-MFG 94.174,62.5 r90 top value=10k
R48 "CRCW060310K0JNEBC" FP-CRCW060310K0JNEBC_0603-MFG 95.674,57 r270 top value=10k
R49 "CRCW060310K0JNEBC" FP-CRCW060310K0JNEBC_0603-MFG 95.674,62.5 r90 top value=10k
R50 "RC0603FR-07100KL" 0603S 103.174,70 r180 top value=100k
R51 "RC0603JR-07510RL" 0603S 99.174,52.5 r90 top value=510
R52 "RC0603FR-07100KL" 0603S 103.174,68.5 r0 top value=100k
R53 "CRCW060310K0JNEBC" FP-CRCW060310K0JNEBC_0603-MFG 94.174,59.5 r90 top value=10k
R54 "CRCW060310K0JNEBC" FP-CRCW060310K0JNEBC_0603-MFG 95.645,59.335 r90 top value=10k
R55 "RC0603JR-0733KL" 0603S 92.16,56.975 r90 top value=33k
R56 "ERJ-6GEYJ4R7V" 0805_HV 102.674,77 r0 top value=4.7
R57 "RC0603JR-07330RL" 0603S 107.9,52.529 r270 top value=330
R58 "RC0603FR-071KL" 0603S 112.674,77.5 r180 top value=1.00k
R59 "RC0603FR-072K2L" 0603S 116.674,65 r90 top value=2.20k
R60 "CRCW060310K0JNEBC" FP-CRCW060310K0JNEBC_0603-MFG 99.674,68.643 r0 top value=10k
R61 "RC0603JR-07680RL" 0603S 91.674,78.5 r90 top value=680
R62 "RC0603JR-07680RL" 0603S 93.674,78.5 r90 top value=680
R63 "RK73H1ETTP47R0F" 0402 124.02,19.211 r270 bottom value=47.0
R64 "D1LPC0402CJUMPF-T10" FP-D1LPC0402CJUMPF-T10_0402-MFG 39.066,40.465 r90 bottom value=0
R65 "D1LPC0402CJUMPF-T10" FP-D1LPC0402CJUMPF-T10_0402-MFG 31.218,15.339 r0 bottom value=0
R66 "D1LPC0402CJUMPF-T10" FP-D1LPC0402CJUMPF-T10_0402-MFG 38.164,40.456 r90 bottom value=0
R67 "D1LPC0402CJUMPF-T10" FP-D1LPC0402CJUMPF-T10_0402-MFG 31.227,16.235 r0 bottom value=0
R68 "D1LPC0402CJUMPF-T10" FP-D1LPC0402CJUMPF-T10_0402-MFG 39.068,50.297 r180 bottom value=0
R69 "D1LPC0402CJUMPF-T10" FP-D1LPC0402CJUMPF-T10_0402-MFG 41.937,15.714 r90 bottom value=0
R70 "D1LPC0402CJUMPF-T10" FP-D1LPC0402CJUMPF-T10_0402-MFG 39.442,49.483 r180 bottom value=0
R71 "D1LPC0402CJUMPF-T10" FP-D1LPC0402CJUMPF-T10_0402-MFG 40.926,15.316 r90 bottom value=0
R72 "ERJ-H2GJ472X" FP-ERJ-H2GJ472X_0402-MFG 40.593,42.269 r270 bottom value=4.7k
R73 "CRCW040247R0JNED" 0402S 41.474,41.935 r90 bottom value=47
R74 "ERJ-H2GJ472X" FP-ERJ-H2GJ472X_0402-MFG 33.382,13.794 r180 bottom value=4.7k
R75 "CRCW040247R0JNED" 0402S 33.22,12.999 r0 bottom value=47
R76 "RC0603JR-07680RL" 0603S 88.174,80.5 r90 top value=680
T1 "070-7148" EP7_7148 64.988,33.929 r0 top
T2 "750510476" Wurth_750510476 65.727,74.903 r180 top value=870uH
TP1 "S2751-46R" Harwin_S2751-46R 72.674,55 r180 top
TP13 "S2751-46R" Harwin_S2751-46R 94.174,34.5 r180 top
TP14 "S2751-46R" Harwin_S2751-46R 91.674,39.5 r180 top
TP15 "S2751-46R" Harwin_S2751-46R 104.5,33 r0 top
TP16 "5001" Keystone5001 14.5,18.5 r90 top
TP17 "5001" Keystone5001 74.853,18.374 r90 top
TP18 "S2751-46R" Harwin_S2751-46R 102.174,79.5 r180 top
TP19 "S2751-46R" Harwin_S2751-46R 118.674,55 r180 top
TP20 "S2751-46R" Harwin_S2751-46R 93.174,48 r270 top
TP21 "S2751-46R" Harwin_S2751-46R 95.674,48 r90 top
TP22 "S2751-46R" Harwin_S2751-46R 100.674,48 r90 top
TP23 "S2751-46R" Harwin_S2751-46R 103.174,48 r90 top
TP24 "S2751-46R" Harwin_S2751-46R 98.174,48 r90 top
TP25 "S2751-46R" Harwin_S2751-46R 99.674,73 r270 top
TP26 "S2751-46R" Harwin_S2751-46R 106.174,79.5 r180 top
TP27 "S2751-46R" Harwin_S2751-46R 109.434,49.775 r90 top
TP28 "S2751-46R" Harwin_S2751-46R 114.674,55 r0 top
U1 "LM74610QDGKRQ1" DGK0008A_N 56.192,61.002 r0 top
U2 "LMG2100R026" VBN0016A-MFG 36.378,44.235 r90 bottom
U3 "LMG2100R026" VBN0016A-MFG 35.288,17.914 r0 bottom
U4 "LMR51410XFDBVR" DBV0006A-MFG 68.824,25.918 r0 top
U5 "LM5164DDAR" DDA0008E-MFG 112,39 r90 bottom
U6 "TPS7A2033PDBVR" DBV0005A-MFG 95.681,36.963 r0 bottom
U7 "TMCS1127B2QDVGR" DVG0010A-MFG 25.625,22.54 r180 top
U8 "INA181A3IDBV" DBV0006A_N 69.064,18.252 r270 top
U9 "TLV9002IDDFR" DDF0008A_N 68.504,46.339 r90 top
U10 "ISOTMP35BEDFQRQ1" DFQ0007A-MFG 122.174,14.2 r270 bottom
U11 "AFE031AIRGZT" RGZ0048B 105.174,59.5 r0 top

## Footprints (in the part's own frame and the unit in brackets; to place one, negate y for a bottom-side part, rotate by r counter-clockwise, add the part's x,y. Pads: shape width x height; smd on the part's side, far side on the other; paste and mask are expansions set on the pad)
0402 [mm] "0402 from SM-752 data"
  rect 0.8x0.6 smd: 1(-0.6,0) 2(0.6,0)
  silkscreen extent -1.22,-0.52 1.22,0.52, body extent -0.55,-0.3 0.55,0.3, height 0.6
0402S [mil] "Based on C0402S footprint from PADS legacy"
  rect 15x24 smd: 1(-20,0) 2(20,0)
  body extent -22,-12 22,12, height 24
0603 [mm] "0603 from SM-752 data"
  rect 1x0.95 smd: 1(-0.8,0) 2(0.8,0)
  silkscreen extent -1.52,-0.69 1.52,0.69, body extent -0.87,-0.47 0.87,0.47, height 1
0603S [mil]
  rect 20x35 smd: 1(-30,0) 2(30,0)
  body extent -34,-19 34,19, height 39
0805_HV [mil] "0805 with 30mil clearance between pads"
  rect 50x63 smd: 1(-40,0) 2(40,0)
  silkscreen extent -74,-40 74,40, body extent -43,-29 43,29, height 57
1206 [mm] "1206 from SM-752 data"
  rect 1.3x1.85 smd: 1(-1.45,0) 2(1.45,0)
  silkscreen extent -2.4,-1.21 2.4,1.21, body extent -1.7,-0.9 1.7,0.9, height 1.35
1206_180 [mm] "1206_180"
  rect 1.1x1.6 smd: 1(-1.7,0) 2(1.7,0)
  silkscreen extent -0.9,-1 0.9,1, body extent -1.75,-0.95 1.75,0.95, height 1.8
1210 [mm] "1210 from SM-752 data"
  rect 1.3x2.7 smd: 1(-1.45,0) 2(1.45,0)
  silkscreen extent -2.32,-1.57 2.32,1.57, body extent -1.7,-1.35 1.7,1.35, height 1.35
CE_Mark_5mm [mm] "Minimum text height for CE Mark"
  silkscreen extent -3.5,-2.5 3.5,2.5
controlCARD-120HSEC [mm] "Pads are not numbered according to Samtec datasheet."
  rect 0.5x2.724 smd: 1(-23.357,-1.678) 2(-23.357,1.722) 3(-22.557,-1.678) 4(-22.557,1.722) 5(-21.757,-1.678) 6(-21.757,1.722) 7(-20.957,-1.678) 8(-20.957,1.722) 9(-20.157,-1.678) 10(-20.157,1.722) 11(-19.357,-1.678) 12(-19.357,1.722) 13(-18.557,-1.678) 14(-18.557,1.722) 15(-17.757,-1.678) 16(-17.757,1.722) 17(-16.957,-1.678) 18(-16.957,1.722) 19(-16.157,-1.678) 20(-16.157,1.722) 21(-15.357,-1.678) 22(-15.357,1.722) 23(-14.557,-1.678) 24(-14.557,1.722) 25(-13.757,-1.678) 26(-13.757,1.722) 27(-12.957,-1.678) 28(-12.957,1.722) 29(-12.157,-1.678) 30(-12.157,1.722) 31(-11.357,-1.678) 32(-11.357,1.722) 33(-10.557,-1.678) 34(-10.557,1.722) 35(-9.757,-1.678) 36(-9.757,1.722) 37(-8.957,-1.678) 38(-8.957,1.722) 39(-8.157,-1.678) 40(-8.157,1.722) 41(-7.357,-1.678) 42(-7.357,1.722) 43(-6.557,-1.678) 44(-6.557,1.722) 45(-5.757,-1.678) 46(-5.757,1.722) 47(-4.957,-1.678) 48(-4.957,1.722) 49(-4.157,-1.678) 50(-4.157,1.722) 51(-3.357,-1.678) 52(-3.357,1.722) 53(-2.557,-1.678) 54(-2.557,1.722) 55(-1.757,-1.678) 56(-1.757,1.722) 57(2.243,-1.678) 58(2.243,1.722) 59(3.043,-1.678) 60(3.043,1.722) 61(3.843,-1.678) 62(3.843,1.722) 63(4.643,-1.678) 64(4.643,1.722) 65(5.443,-1.678) 66(5.443,1.722) 67(6.243,-1.678) 68(6.243,1.722) 69(7.043,-1.678) 70(7.043,1.722) 71(7.843,-1.678) 72(7.843,1.722) 73(8.643,-1.678) 74(8.643,1.722) 75(9.443,-1.678) 76(9.443,1.722) 77(10.243,-1.678) 78(10.243,1.722) 79(11.043,-1.678) 80(11.043,1.722) 81(11.843,-1.678) 82(11.843,1.722) 83(12.643,-1.678) 84(12.643,1.722) 85(13.443,-1.678) 86(13.443,1.722) 87(14.243,-1.678) 88(14.243,1.722) 89(15.043,-1.678) 90(15.043,1.722) 91(15.843,-1.678) 92(15.843,1.722) 93(16.643,-1.678) 94(16.643,1.722) 95(17.443,-1.678) 96(17.443,1.722) 97(18.243,-1.678) 98(18.243,1.722) 99(19.043,-1.678) 100(19.043,1.722) 101(19.843,-1.678) 102(19.843,1.722) 103(20.643,-1.678) 104(20.643,1.722) 105(21.443,-1.678) 106(21.443,1.722) 107(22.243,-1.678) 108(22.243,1.722) 109(23.043,-1.678) 110(23.043,1.722) 111(23.843,-1.678) 112(23.843,1.722) 113(24.643,-1.678) 114(24.643,1.722) 115(25.443,-1.678) 116(25.443,1.722) 117(26.243,-1.678) 118(26.243,1.722) 119(27.043,-1.678) 120(27.043,1.722)
  round 0.025 hole 1.27 unplated mask+0.876: 181(-24.857,0.022) 182(28.543,1.522)
  round 1.348 hole 0.84: 185(-27.207,0.022) 186(30.893,0.022)
  silkscreen extent -32.11,-3.86 35.8,3.9, body extent -31.75,-3.48 35.3,3.52, height 12.35
DBV0005A-MFG [mm]
  rrect17% 1.1x0.6 smd paste+0 mask+0: 1(-1.3,0.95) 2(-1.3,0) 3(-1.3,-0.95) 4(1.3,-0.95) 5(1.3,0.95)
  silkscreen extent -2.57,-1.53 0.87,1.53, body extent -1.4,-1.45 1.4,1.45, height 1.45
DBV0006A-MFG [mm]
  rrect17% 1.1x0.6 smd paste+0 mask+0: 1(-1.3,0.95) 2(-1.3,0) 3(-1.3,-0.95) 4(1.3,-0.95) 5(1.3,0) 6(1.3,0.95)
  silkscreen extent -2.52,-1.53 0.35,1.53, body extent -1.95,-1.78 1.95,1.78, height 0.25
DBV0006A_N [mm] "SOT23, 6-Leads, Body 2.9x1.6mm, Pitch 0.95mm, Lead Span 2.8mm, IPC Medium Density"
  rrect17% 1x0.6 smd: 1(-1.375,0.95) 2(-1.375,0) 3(-1.375,-0.95) 4(1.375,-0.95) 5(1.375,0) 6(1.375,0.95)
  silkscreen extent -1.68,-1.55 0.5,1.55, body extent -1.42,-1.46 1.42,1.46, height 1.12
DDA0008E-MFG [mm]
  rrect20% 2.2x0.5 smd paste-1000 mask+0: 1(-2.875,1.905) 2(-2.875,0.635) 3(-2.875,-0.635) 4(-2.875,-1.905) 5(2.875,-1.905) 6(2.875,-0.635) 7(2.875,0.635) 8(2.875,1.905)
  rrect3% 2.95x4.9 smd paste-1000 mask-1000: 9(0,0)
  silkscreen extent -4.67,-2.83 2,2.83, body extent -3,-2.45 3,2.45, height 1.7
DDF0008A_N [mm] "SOT-23-THN-8, IPC Medium Density"
  oval 1x0.45 smd: 1(-1.35,0.975) 2(-1.35,0.325) 3(-1.35,-0.325) 4(-1.35,-0.975) 5(1.35,-0.975) 6(1.35,-0.325) 7(1.35,0.325) 8(1.35,0.975)
  body extent -1.41,-1.45 1.41,1.45, height 0.9
DFQ0007A-MFG [mm]
  rrect17% 1.55x0.6 smd paste+0 mask+0: 1(-2.7,1.905) 2(-2.7,0.635) 3(-2.7,-0.635) 4(-2.7,-1.905) 5(2.7,-1.905) 7(2.7,1.905)
  rrect6% 1.55x2.36 smd paste+0 mask+0: 6(2.7,0)
  silkscreen extent -4.14,-2.5 1.55,2.5, body extent -3.01,-2.45 3.01,2.45, height 1.75
DGK0008A_N [mm] "TSOP, 8-Leads, Body 3x3mm, Pitch 0.65mm, IPC Medium Density"
  oval 1.35x0.45 smd: 1(-2.225,0.975) 2(-2.225,0.325) 3(-2.225,-0.325) 4(-2.225,-0.975) 5(2.225,-0.975) 6(2.225,-0.325) 7(2.225,0.325) 8(2.225,0.975)
  silkscreen extent -2.75,-1.55 0.95,1.55, body extent -2.45,-1.5 2.45,1.5, height 0.96
DNK0008A [mm] "SON, 8-Leads, Body 5x6mm"
  rrect39% 0.86x0.51 smd paste-0.05 mask-0.05: 1(-2.82,1.905) 2(-2.82,0.635) 3(-2.82,-0.635) 4(-2.82,-1.905) 5(2.82,-1.905) 6(2.82,-0.635) 7(2.82,0.635) 8(2.82,1.905)
  rrect40% 0.25x0.555 on Top Solder: 9(-0.83,2.372) 9(-0.83,-2.372)
  rrect40% 0.25x0.555 on Top Paste: 9(-0.83,2.372) 9(-0.83,-2.372)
  rrect11% 0.95x1.13 on Top Paste: 9(-0.535,1.33) 9(-0.535,0) 9(-0.535,-1.33) 9(0.615,1.33) 9(0.615,0) 9(0.615,-1.33) 9(1.765,-1.33) 9(1.765,0) 9(1.765,1.33)
  rrect3% 3.58x4 on Top Solder: 9(0.75,0)
  rrect5% 4.34x5.4 smd paste-3 mask-3: 9(1.08,0)
  body extent -3.05,-2.55 3.05,2.55, height 1.06
DO1607B [mm] "Coilcraft"
  rect 1.4x3.56 smd: 1(-2.73,0) 2(2.73,0)
  silkscreen extent -1.78,-2.32 1.79,2.32, body extent -3.3,-2.22 3.3,2.23, height 2.53
DVG0010A-MFG [mm]
  rrect6% 1.65x4.41 smd paste+0 mask+0: 1(-4.875,2.54) 2(-4.875,-2.54)
  rrect17% 1.65x0.6 smd paste+0 mask+0: 3(4.875,-4.445) 4(4.875,-3.175) 5(4.875,-1.905) 6(4.875,-0.635) 7(4.875,0.635) 8(4.875,1.905) 9(4.875,3.175) 10(4.875,4.445)
  silkscreen extent -6.38,-5.25 3.67,5.25, body extent -5.8,-5.5 5.8,5.5, height 0.25
EP7_7148 [mm] "SMD, 8-Leads, Body 9.78x9.14mm, Pitch 2.49mm, IPC Medium Density"
  rect 1.91x1.17 smd: 1(4.065,3.735) 2(4.065,1.245) 3(4.065,-1.245) 4(4.065,-3.735) 5(-4.065,-3.735) 6(-4.065,-1.245) 7(-4.065,1.245) 8(-4.065,3.735)
  silkscreen extent -2.5,-4.9 5.88,5.56, body extent -4.68,-4.97 4.48,4.85, height 10.1
FCC_disclaimer [mm]
FP-0805YC106KAT2A_0805-MFG [mm]
  rrect10% 1x1.25 smd paste+0 mask+0: 1(-1,0) 2(1,0)
  silkscreen extent -0.13,-0.72 0.13,0.72, body extent -1.6,-0.82 1.6,0.82, height 0.25
FP-04025U100FAT2A_0402-MFG [mm]
  rrect20% 0.6x0.5 smd paste+0 mask+0: 1(-0.55,0) 2(0.55,0)
  body extent -0.95,-0.4 0.95,0.4, height 0.25
FP-06031C104K4T2A_0603-MFG [mm]
  rrect13% 0.8x0.75 smd paste+0 mask+0: 1(-0.75,0) 2(0.75,0)
  silkscreen extent -0.87,-0.75 0.87,0.75, body extent -0.8,-0.41 0.8,0.41, height 0.94
FP-06031C332J4Z2A_0603-MFG [mm]
  rrect13% 0.8x0.75 smd paste+0 mask+0: 1(-0.75,0) 2(0.75,0)
  silkscreen extent -0.87,0.8 0.87,0.8, body extent -1.25,-0.58 1.25,0.58, height 0.25
FP-C0402C101J4GAC7867_0402-MFG [mm]
  rrect19% 0.52x0.52 smd paste+0 mask+0: 1(-0.4,0) 2(0.4,0)
  silkscreen extent -0.53,-0.64 0.53,0.64, body extent -0.5,-0.25 0.5,0.25, height 0.55
FP-C0603X102K5RAC7867_0603-MFG [mm]
  rrect12% 0.85x0.9 smd paste+0 mask+0: 1(-0.65,0) 2(0.65,0)
  silkscreen extent -0.88,-0.82 0.88,0.82, body extent -1.2,-0.6 1.2,0.6, height 0.25
FP-CGA9N3X7R1E476M230KB_2220-MFG [mm]
  rrect8% 1.3x4.5 smd paste+0 mask+0: 1(-2.875,0) 2(2.875,0)
  silkscreen extent -3.05,-2.7 3.05,2.7, body extent -3.62,-2.8 3.62,2.8, height 0.25
FP-CR0402-10W-000T_0402-MFG [mm]
  rrect17% 0.8x0.6 smd paste+0 mask+0: 1(-0.6,0) 2(0.6,0)
  silkscreen extent -0.53,-0.7 0.53,0.7, body extent -0.5,-0.25 0.5,0.25, height 0.4
FP-CRCW060310K0JNEBC_0603-MFG [mm]
  rrect20% 0.5x0.9 smd paste+0 mask+0: 1(-0.75,0) 2(0.75,0)
  silkscreen extent -0.13,-0.45 0.13,0.45, body extent -1.1,-0.55 1.1,0.55, height 0.25
FP-D1LPC0402CJUMPF-T10_0402-MFG [mm]
  rrect17% 0.6x0.6 smd paste+0 mask+0: 1(-0.5,0) 2(0.5,0)
  body extent -0.5,-0.25 0.5,0.25, height 0.45
FP-ERJ-H2GJ472X_0402-MFG [mm]
  rrect21% 0.475x0.5 smd paste+0 mask+0: 1(-0.512,0) 2(0.513,0)
  body extent -0.5,-0.25 0.5,0.25, height 0.4
FP-GCJ188R71C104KA01D_0603-MFG [mm]
  rrect15% 0.65x0.7 smd paste+0 mask+0: 1(-0.675,0) 2(0.675,0)
  silkscreen extent -0.9,-0.79 0.9,0.77, body extent -1.1,-0.55 1.1,0.55, height 0.25
FP-GCM188D71H105KE36J_0603-MFG [mm]
  rrect13% 0.75x0.9 smd paste+0 mask+0: 1(-0.775,0) 2(0.775,0)
  silkscreen extent 0,-0.5 0,0.5, body extent -1.25,-0.6 1.25,0.6, height 0.25
FP-GRM32EC72A106KE05L_1210-MFG [mm]
  rrect9% 1.1x2.05 smd paste+0 mask+0: 1(-1.65,0) 2(1.65,0)
  silkscreen extent -0.72,-1.35 0.72,1.35, body extent -2.3,-1.45 2.3,1.45, height 0.25
FP-GRM188C71C225KE11D_0603-MFG [mm]
  rrect13% 0.75x0.9 smd paste+0 mask+0: 1(-0.775,0) 2(0.775,0)
  body extent -1.25,-0.6 1.25,0.6, height 0.25
FP-GRT155R61E105KE01D_0402-MFG [mm]
  rrect25% 0.4x0.5 smd paste+0 mask+0: 1(-0.4,0) 2(0.4,0)
  body extent -0.5,-0.25 0.5,0.25, height 0.55
FP-GRT1555C1E101JA02D_0402-MFG [mm]
  rrect25% 0.4x0.5 smd paste+0 mask+0: 1(-0.4,0) 2(0.4,0)
  body extent -0.5,-0.25 0.5,0.25, height 0.55
FP-MH1608-601Y_0603-MFG [mm]
  rrect14% 0.7x0.7 smd paste+0 mask+0: 1(-0.7,0) 2(0.7,0)
  silkscreen extent -0.87,-0.8 0.87,0.8, body extent -0.8,-0.4 0.8,0.4, height 1
FP-RT0603BRD071KL_0603-MFG [mm]
  rrect13% 0.9x0.8 smd paste+0 mask+0: 1(-0.85,0) 2(0.85,0)
  silkscreen extent -0.85,-0.78 0.86,0.77, body extent -0.8,-0.4 0.8,0.4, height 0.57
FP-ULRG32512R001FLFSLT_2512-MFG [mm]
  rrect4% 2.38x3.45 smd paste+0 mask+0: 1(-2.21,0) 2(2.21,0)
  silkscreen extent -0.64,-1.6 0.64,1.6, body extent -3.5,-1.83 3.5,1.83, height 0.25
Harwin_S2751-46R [mm] "Test Point, SMT"
  rect 2.2x1.4 smd: 1(0,0)
  body extent -1,-0.6 1,0.6, height 1.4
Keystone5001 [mil] "For Keystone 500x miniature loop terminals"
  round 80 hole 40: 1(0,0)
  silkscreen extent -52,-52 52,52, body extent -49,-49 49,49, height 182
Keystone_1902C [mil] "Hex Standoff, 4-40 threaded, nylon"
  round 1 on Mech4: 0(0,0)
  body extent -145,-126 146,126, height 501
Label_650x200 [mil] "Thermal Transfer Label"
  round 1 on Mech13: 0(0,0)
  silkscreen extent -325,-100 325,100, body extent -325,-100 325,100, height 1
LQH2MC_52 [mm] "MuRata"
  rect 0.9x1 smd: 1(-0.85,0) 2(0.85,0)
  silkscreen extent -1,-1 1,1, body extent -1.1,-0.9 1.1,0.9, height 0.7
"NY PMS 440 0025 PH" [mm] "4-40 nylon screw and mounting hole"
  round 8 hole 3.2: 1(0,0)
  body extent -3.3,-3.3 3.3,3.3, height 2.69
On-Shore_OSTT7020150 [mm] "Terminal Block, 6.35mm, 2x1, TH"
  rrect50% 2.1x2.1 hole 1.6: 1(-3.175,0)
  round 2.1 hole 1.6: 2(3.175,0)
  silkscreen extent -6.98,-8 6.35,5, body extent -6.98,-8 6.35,4.5, height 21.5
RGZ0048B [mm] "QFN, 48-Leads, Body 7x7mm, Pitch 0.5mm, Thermal Pad 5.15x5.15mm, TI Recommended"
  rrect42% 0.6x0.24 smd: 1(-3.4,2.75) 2(-3.4,2.25) 3(-3.4,1.75) 4(-3.4,1.25) 5(-3.4,0.75) 6(-3.4,0.25) 7(-3.4,-0.25) 8(-3.4,-0.75) 9(-3.4,-1.25) 10(-3.4,-1.75) 11(-3.4,-2.25) 12(-3.4,-2.75) 25(3.4,-2.75) 26(3.4,-2.25) 27(3.4,-1.75) 28(3.4,-1.25) 29(3.4,-0.75) 30(3.4,-0.25) 31(3.4,0.25) 32(3.4,0.75) 33(3.4,1.25) 34(3.4,1.75) 35(3.4,2.25) 36(3.4,2.75)
  rrect42% 0.24x0.6 smd: 13(-2.75,-3.4) 14(-2.25,-3.4) 15(-1.75,-3.4) 16(-1.25,-3.4) 17(-0.75,-3.4) 18(-0.25,-3.4) 19(0.25,-3.4) 20(0.75,-3.4) 21(1.25,-3.4) 22(1.75,-3.4) 23(2.25,-3.4) 24(2.75,-3.4) 37(2.75,3.4) 38(2.25,3.4) 39(1.75,3.4) 40(1.25,3.4) 41(0.75,3.4) 42(0.25,3.4) 43(-0.25,3.4) 44(-0.75,3.4) 45(-1.25,3.4) 46(-1.75,3.4) 47(-2.25,3.4) 48(-2.75,3.4)
  rrect9% 1.17x1.17 on Top Paste: 49(-1.37,-1.37) 49(-1.37,0) 49(-1.37,1.37) 49(0,-1.37) 49(0,0) 49(0,1.37) 49(1.37,-1.37) 49(1.37,0) 49(1.37,1.37)
  rrect2% 4.1x4.1 smd paste-2.575: 49(0,0)
  silkscreen extent -3.72,-3.72 3.72,3.72, body extent -3.5,-3.5 3.5,3.5, height 1.01
SER2013 [mil] "Coilcraft recommended land pattern.  Document 349-1, rev 02/24/10"
  rect 185x150 smd: 1(-352.25,205) 2(-352.25,-205)
  rect 160x290 smd: 3(290.25,0)
  silkscreen extent -193,-394 193,394, body extent -412,-390 324,390, height 510
SMA [mm] "Molded Diode, 2-Leads, Body 4.3x2.6mm, IPC Medium Density, based on OnSemi component dimensions and land pattern"
  rect 2x2 smd: 1(-2,0) 2(2,0)
  silkscreen extent -3.66,-1.57 2.79,1.57, body extent -2.6,-1.3 2.6,1.3, height 2.42
SMA_Bi [mm] "SMD, 2-Leads, Body 4.275x2.575mm"
  rect 1.4x1.64 smd: 1(-2.015,0) 2(2.015,0)
  silkscreen extent -2.3,-1.45 2.3,1.45, body extent -2.52,-1.45 2.52,1.45, height 2.65
SOD-123 [mm] "On Semi recommended land pattern"
  rect 0.915x1.22 smd: 1(-1.637,0) 2(1.637,0)
  silkscreen extent -2.74,-1.17 2.03,1.17, body extent -1.93,-0.9 1.93,0.9, height 1.35
SOT-23 [mm] "SOT23, 3-Leads, Body 2.9x1.3mm, Pitch 0.95mm, Lead Span 2.5mm, IPC Medium Density"
  rrect50% 1x0.6 smd: 1(-1.2,0.95) 2(-1.2,-0.95) 3(1.2,0)
  silkscreen extent -1.62,-1.5 0.7,1.5, body extent -1.16,-1.45 1.21,1.45, height 1
TI_Stacked_Overlay_Small [mm]
  silkscreen extent -10.63,-2.49 10.63,2.49
TSW-108-07-G-S [mm] "Samtec 100mil, 1x8, 230 mil above insulator"
  rrect6% 1.65x1.65 hole 1.016: 1(-8.89,0)
  round 1.65 hole 1.016: 2(-6.35,0) 3(-3.81,0) 4(-1.27,0) 5(1.27,0) 6(3.81,0) 7(6.35,0) 8(8.89,0)
  silkscreen extent -10.16,-1.27 10.16,1.65, body extent -10.16,-1.27 10.16,1.27, height 8.38
VBN0016A-MFG [mm]
  round 0.228 smd paste+0 mask+0: 1(-1.925,3.125) 11(1.925,3.125)
  rrect40% 0.7x0.25 smd paste+0 mask+0: 2(-2.1,2.575) 3(-2.1,2.075) 4(-2.1,1.575) 8(2.1,1.575) 9(2.1,2.075) 10(2.1,2.575)
  round 0.394 smd paste+0 mask+0: 5(-1.969,-1.335) 7(1.969,-1.335)
  rrect8% 2.35x1.33 smd paste-1000 mask+0: 6(-0.225,1.985)
  round 1.603 smd paste-1000 mask+0: 6(-0.059,-2.453)
  rrect5% 1.9x1.976 smd paste-1000 mask+0: 6(0,0.032)
  rrect40% 0.25x0.7 smd paste+0 mask+0: 12(0.825,3.35) 13(0.325,3.35) 14(-0.175,3.35) 15(-0.675,3.35) 16(-1.175,3.35)
  Power1 region: -2.4,2.95 -2.419,2.954 -2.435,2.965 -2.446,2.981 -2.45,3 -2.45,3 -2.45,3.15 -2.443,3.175 -2.425,3.193 -2.4,3.2 -2.4,3.2 -2.05,3.2 -2.031,3.204 -2.015,3.215 -2.004,3.231 -2,3.25 -2,3.25 -2,3.65 -1.993,3.675 -1.975,3.693 -1.95,3.7 -1.95,3.7 -1.8,3.7 -1.781,3.696 -1.765,3.685 -1.754,3.669 -1.75,3.65 -1.75,3.65 -1.75,3 -1.754,2.981 -1.765,2.965 -1.781,2.954 -1.8,2.95 -1.8,2.95
  Power1 region: 2.4,2.95 2.419,2.954 2.435,2.965 2.446,2.981 2.45,3 2.45,3 2.45,3.15 2.446,3.169 2.435,3.185 2.419,3.196 2.4,3.2 2.4,3.2 2.05,3.2 2.025,3.207 2.007,3.225 2,3.25 2,3.25 2,3.65 1.996,3.669 1.985,3.685 1.969,3.696 1.95,3.7 1.95,3.7 1.8,3.7 1.781,3.696 1.765,3.685 1.754,3.669 1.75,3.65 1.75,3.65 1.75,3 1.754,2.981 1.765,2.965 1.781,2.954 1.8,2.95 1.8,2.95
  Power1 region: -0.55,-3.65 -0.554,-3.669 -0.565,-3.685 -0.581,-3.696 -0.6,-3.7 -0.6,-3.7 -0.75,-3.7 -0.775,-3.693 -0.793,-3.675 -0.8,-3.65 -0.8,-3.65 -0.8,-3.425 -0.804,-3.406 -0.815,-3.39 -0.831,-3.379 -0.85,-3.375 -0.85,-3.375 -0.9,-3.375 -0.925,-3.368 -0.943,-3.35 -0.95,-3.325 -0.95,-3.325 -0.95,-1.506 -0.943,-1.481 -0.925,-1.463 -0.9,-1.456 -0.9,-1.456 0.9,-1.456 0.919,-1.46 0.935,-1.471 0.946,-1.487 0.95,-1.506 0.95,-1.506 0.95,-3.325 0.943,-3.35 0.925,-3.368 0.9,-3.375 0.9,-3.375 0.5,-3.375 0.481,-3.379 0.465,-3.39 0.454,-3.406 0.45,-3.425 0.45,-3.425 0.45,-3.65 0.443,-3.675 0.425,-3.693 0.4,-3.7 0.4,-3.7 0.25,-3.7 0.231,-3.696 0.215,-3.685 0.204,-3.669 0.2,-3.65 0.2,-3.65 0.2,-3.425 0.196,-3.406 0.185,-3.39 0.169,-3.379 0.15,-3.375 0.15,-3.375 0,-3.375 -0.019,-3.379 -0.035,-3.39 -0.046,-3.406 -0.05,-3.425 -0.05,-3.425 -0.05,-3.65 -0.054,-3.669 -0.065,-3.685 -0.081,-3.696 -0.1,-3.7 -0.1,-3.7 -0.25,-3.7 -0.275,-3.693 -0.293,-3.675 -0.3,-3.65 -0.3,-3.65 -0.3,-3.425 -0.304,-3.406 -0.315,-3.39 -0.331,-3.379 -0.35,-3.375 -0.35,-3.375 -0.5,-3.375 -0.519,-3.379 -0.535,-3.39 -0.546,-3.406 -0.55,-3.425 -0.55,-3.425
  Power1 region: -2.075,0.542 -2.1,0.535 -2.118,0.517 -2.125,0.492 -2.125,0.492 -2.125,0.338 -2.129,0.319 -2.14,0.303 -2.156,0.292 -2.175,0.288 -2.175,0.288 -2.4,0.288 -2.425,0.281 -2.443,0.263 -2.45,0.238 -2.45,0.238 -2.45,0.088 -2.443,0.063 -2.425,0.045 -2.4,0.038 -2.4,0.038 -2.175,0.038 -2.15,0.031 -2.132,0.013 -2.125,-0.012 -2.125,-0.012 -2.125,-0.162 -2.132,-0.187 -2.15,-0.205 -2.175,-0.212 -2.175,-0.212 -2.4,-0.212 -2.419,-0.216 -2.435,-0.227 -2.446,-0.243 -2.45,-0.262 -2.45,-0.262 -2.45,-0.412 -2.443,-0.437 -2.425,-0.455 -2.4,-0.462 -2.4,-0.462 -2.175,-0.462 -2.156,-0.466 -2.14,-0.477 -2.129,-0.493 -2.125,-0.512 -2.125,-0.512 -2.125,-0.662 -2.129,-0.681 -2.14,-0.697 -2.156,-0.708 -2.175,-0.712 -2.175,-0.712 -2.4,-0.712 -2.419,-0.716 -2.435,-0.727 -2.446,-0.743 -2.45,-0.762 -2.45,-0.762 -2.45,-0.912 -2.443,-0.937 -2.425,-0.955 -2.4,-0.962 -2.4,-0.962 -2.175,-0.962 -2.156,-0.966 -2.14,-0.977 -2.129,-0.993 -2.125,-1.012 -2.125,-1.012 -2.125,-1.162 -2.129,-1.181 -2.14,-1.197 -2.156,-1.208 -2.175,-1.212 -2.175,-1.212 -2.4,-1.212 -2.419,-1.216 -2.435,-1.227 -2.446,-1.243 -2.45,-1.262 -2.45,-1.262 -2.45,-1.412 -2.443,-1.437 -2.425,-1.455 -2.4,-1.462 -2.4,-1.462 -2.175,-1.462 -2.156,-1.466 -2.14,-1.477 -2.129,-1.493 -2.125,-1.512 -2.125,-1.512 -2.125,-1.662 -2.129,-1.681 -2.14,-1.697 -2.156,-1.708 -2.175,-1.712 -2.175,-1.712 -2.4,-1.712 -2.419,-1.716 -2.435,-1.727 -2.446,-1.743 -2.45,-1.762 -2.45,-1.762 -2.45,-1.912 -2.443,-1.937 -2.425,-1.955 -2.4,-1.962 -2.4,-1.962 -2.175,-1.962 -2.156,-1.966 -2.14,-1.977 -2.129,-1.993 -2.125,-2.012 -2.125,-2.012 -2.125,-2.162 -2.129,-2.181 -2.14,-2.197 -2.156,-2.208 -2.175,-2.212 -2.175,-2.212 -2.4,-2.212 -2.419,-2.216 -2.435,-2.227 -2.446,-2.243 -2.45,-2.262 -2.45,-2.262 -2.45,-2.412 -2.443,-2.437 -2.425,-2.455 -2.4,-2.462 -2.4,-2.462 -2.175,-2.462 -2.156,-2.466 -2.14,-2.477 -2.129,-2.493 -2.125,-2.512 -2.125,-2.512 -2.125,-2.662 -2.129,-2.681 -2.14,-2.697 -2.156,-2.708 -2.175,-2.712 -2.175,-2.712 -2.4,-2.712 -2.419,-2.716 -2.435,-2.727 -2.446,-2.743 -2.45,-2.762 -2.45,-2.762 -2.45,-2.912 -2.443,-2.937 -2.425,-2.955 -2.4,-2.962 -2.4,-2.962 -2.175,-2.962 -2.156,-2.966 -2.14,-2.977 -2.129,-2.993 -2.125,-3.012 -2.125,-3.012 -2.125,-3.166 -2.118,-3.191 -2.1,-3.209 -2.075,-3.216 -2.075,-3.216 -1.8,-3.216 -1.781,-3.212 -1.765,-3.201 -1.754,-3.185 -1.75,-3.166 -1.75,-3.166 -1.75,0.492 -1.754,0.511 -1.765,0.527 -1.781,0.538 -1.8,0.542 -1.8,0.542
  Power1 region: 2.075,0.542 2.094,0.538 2.11,0.527 2.121,0.511 2.125,0.492 2.125,0.492 2.125,0.338 2.129,0.319 2.14,0.303 2.156,0.292 2.175,0.288 2.175,0.288 2.4,0.288 2.419,0.284 2.435,0.273 2.446,0.257 2.45,0.238 2.45,0.238 2.45,0.088 2.443,0.063 2.425,0.045 2.4,0.038 2.4,0.038 2.175,0.038 2.156,0.034 2.14,0.023 2.129,0.007 2.125,-0.012 2.125,-0.012 2.125,-0.162 2.132,-0.187 2.15,-0.205 2.175,-0.212 2.175,-0.212 2.4,-0.212 2.425,-0.219 2.443,-0.237 2.45,-0.262 2.45,-0.262 2.45,-0.412 2.446,-0.431 2.435,-0.447 2.419,-0.458 2.4,-0.462 2.4,-0.462 2.175,-0.462 2.156,-0.466 2.14,-0.477 2.129,-0.493 2.125,-0.512 2.125,-0.512 2.125,-0.662 2.129,-0.681 2.14,-0.697 2.156,-0.708 2.175,-0.712 2.175,-0.712 2.4,-0.712 2.419,-0.716 2.435,-0.727 2.446,-0.743 2.45,-0.762 2.45,-0.762 2.45,-0.912 2.446,-0.931 2.435,-0.947 2.419,-0.958 2.4,-0.962 2.4,-0.962 2.175,-0.962 2.156,-0.966 2.14,-0.977 2.129,-0.993 2.125,-1.012 2.125,-1.012 2.125,-1.162 2.129,-1.181 2.14,-1.197 2.156,-1.208 2.175,-1.212 2.175,-1.212 2.4,-1.212 2.419,-1.216 2.435,-1.227 2.446,-1.243 2.45,-1.262 2.45,-1.262 2.45,-1.412 2.446,-1.431 2.435,-1.447 2.419,-1.458 2.4,-1.462 2.4,-1.462 2.175,-1.462 2.156,-1.466 2.14,-1.477 2.129,-1.493 2.125,-1.512 2.125,-1.512 2.125,-1.662 2.129,-1.681 2.14,-1.697 2.156,-1.708 2.175,-1.712 2.175,-1.712 2.4,-1.712 2.419,-1.716 2.435,-1.727 2.446,-1.743 2.45,-1.762 2.45,-1.762 2.45,-1.912 2.446,-1.931 2.435,-1.947 2.419,-1.958 2.4,-1.962 2.4,-1.962 2.175,-1.962 2.156,-1.966 2.14,-1.977 2.129,-1.993 2.125,-2.012 2.125,-2.012 2.125,-2.162 2.129,-2.181 2.14,-2.197 2.156,-2.208 2.175,-2.212 2.175,-2.212 2.4,-2.212 2.419,-2.216 2.435,-2.227 2.446,-2.243 2.45,-2.262 2.45,-2.262 2.45,-2.412 2.446,-2.431 2.435,-2.447 2.419,-2.458 2.4,-2.462 2.4,-2.462 2.175,-2.462 2.156,-2.466 2.14,-2.477 2.129,-2.493 2.125,-2.512 2.125,-2.512 2.125,-2.662 2.129,-2.681 2.14,-2.697 2.156,-2.708 2.175,-2.712 2.175,-2.712 2.4,-2.712 2.419,-2.716 2.435,-2.727 2.446,-2.743 2.45,-2.762 2.45,-2.762 2.45,-2.912 2.446,-2.931 2.435,-2.947 2.419,-2.958 2.4,-2.962 2.4,-2.962 2.175,-2.962 2.156,-2.966 2.14,-2.977 2.129,-2.993 2.125,-3.012 2.125,-3.012 2.125,-3.166 2.121,-3.185 2.11,-3.201 2.094,-3.212 2.075,-3.216 2.075,-3.216 1.8,-3.216 1.775,-3.209 1.757,-3.191 1.75,-3.166 1.75,-3.166 1.75,0.492 1.754,0.511 1.765,0.527 1.781,0.538 1.8,0.542 1.8,0.542
  silkscreen extent -2.98,-3.88 2.63,3.88, body extent -2.25,-3.5 2.25,3.5, height 0.85
WE-PD2SA_7850 [mm] "SMD Power Inductor, body 7.8x7mm"
  rect 3x7.5 smd: 1(-2.5,0) 2(2.5,0)
  silkscreen extent -4.62,-3.65 0.65,3.65, body extent -3.9,-3.5 3.9,3.5, height 5
WEEE_Minimum [mm] "WEEElie bin"
  silkscreen extent -2.42,-4.38 2.52,2.65
WL-SMCW_Blue [mm] "SMD, 2-Leads, Body 1.6x0.8mm"
  rect 0.8x0.8 smd: 1(-0.8,0) 2(0.8,0)
  silkscreen extent -1.9,-0.8 1.2,0.8, body extent -0.85,-0.45 0.85,0.45, height 0.8
WL-SMCW_RED [mm] "WURTH"
  rect 0.8x0.8 smd: 1(-0.8,0) 2(0.8,0)
  silkscreen extent -1.9,-0.8 1.2,0.8, body extent -0.85,-0.45 0.85,0.45, height 0.8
